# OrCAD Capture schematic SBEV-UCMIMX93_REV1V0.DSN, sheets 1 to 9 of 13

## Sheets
1 01 Index and Block Diagram: title: SBEV-UCMIMX93   01. INDEX AND BLOCK DIAGRAM; rev: 1.0; note: 8000245000
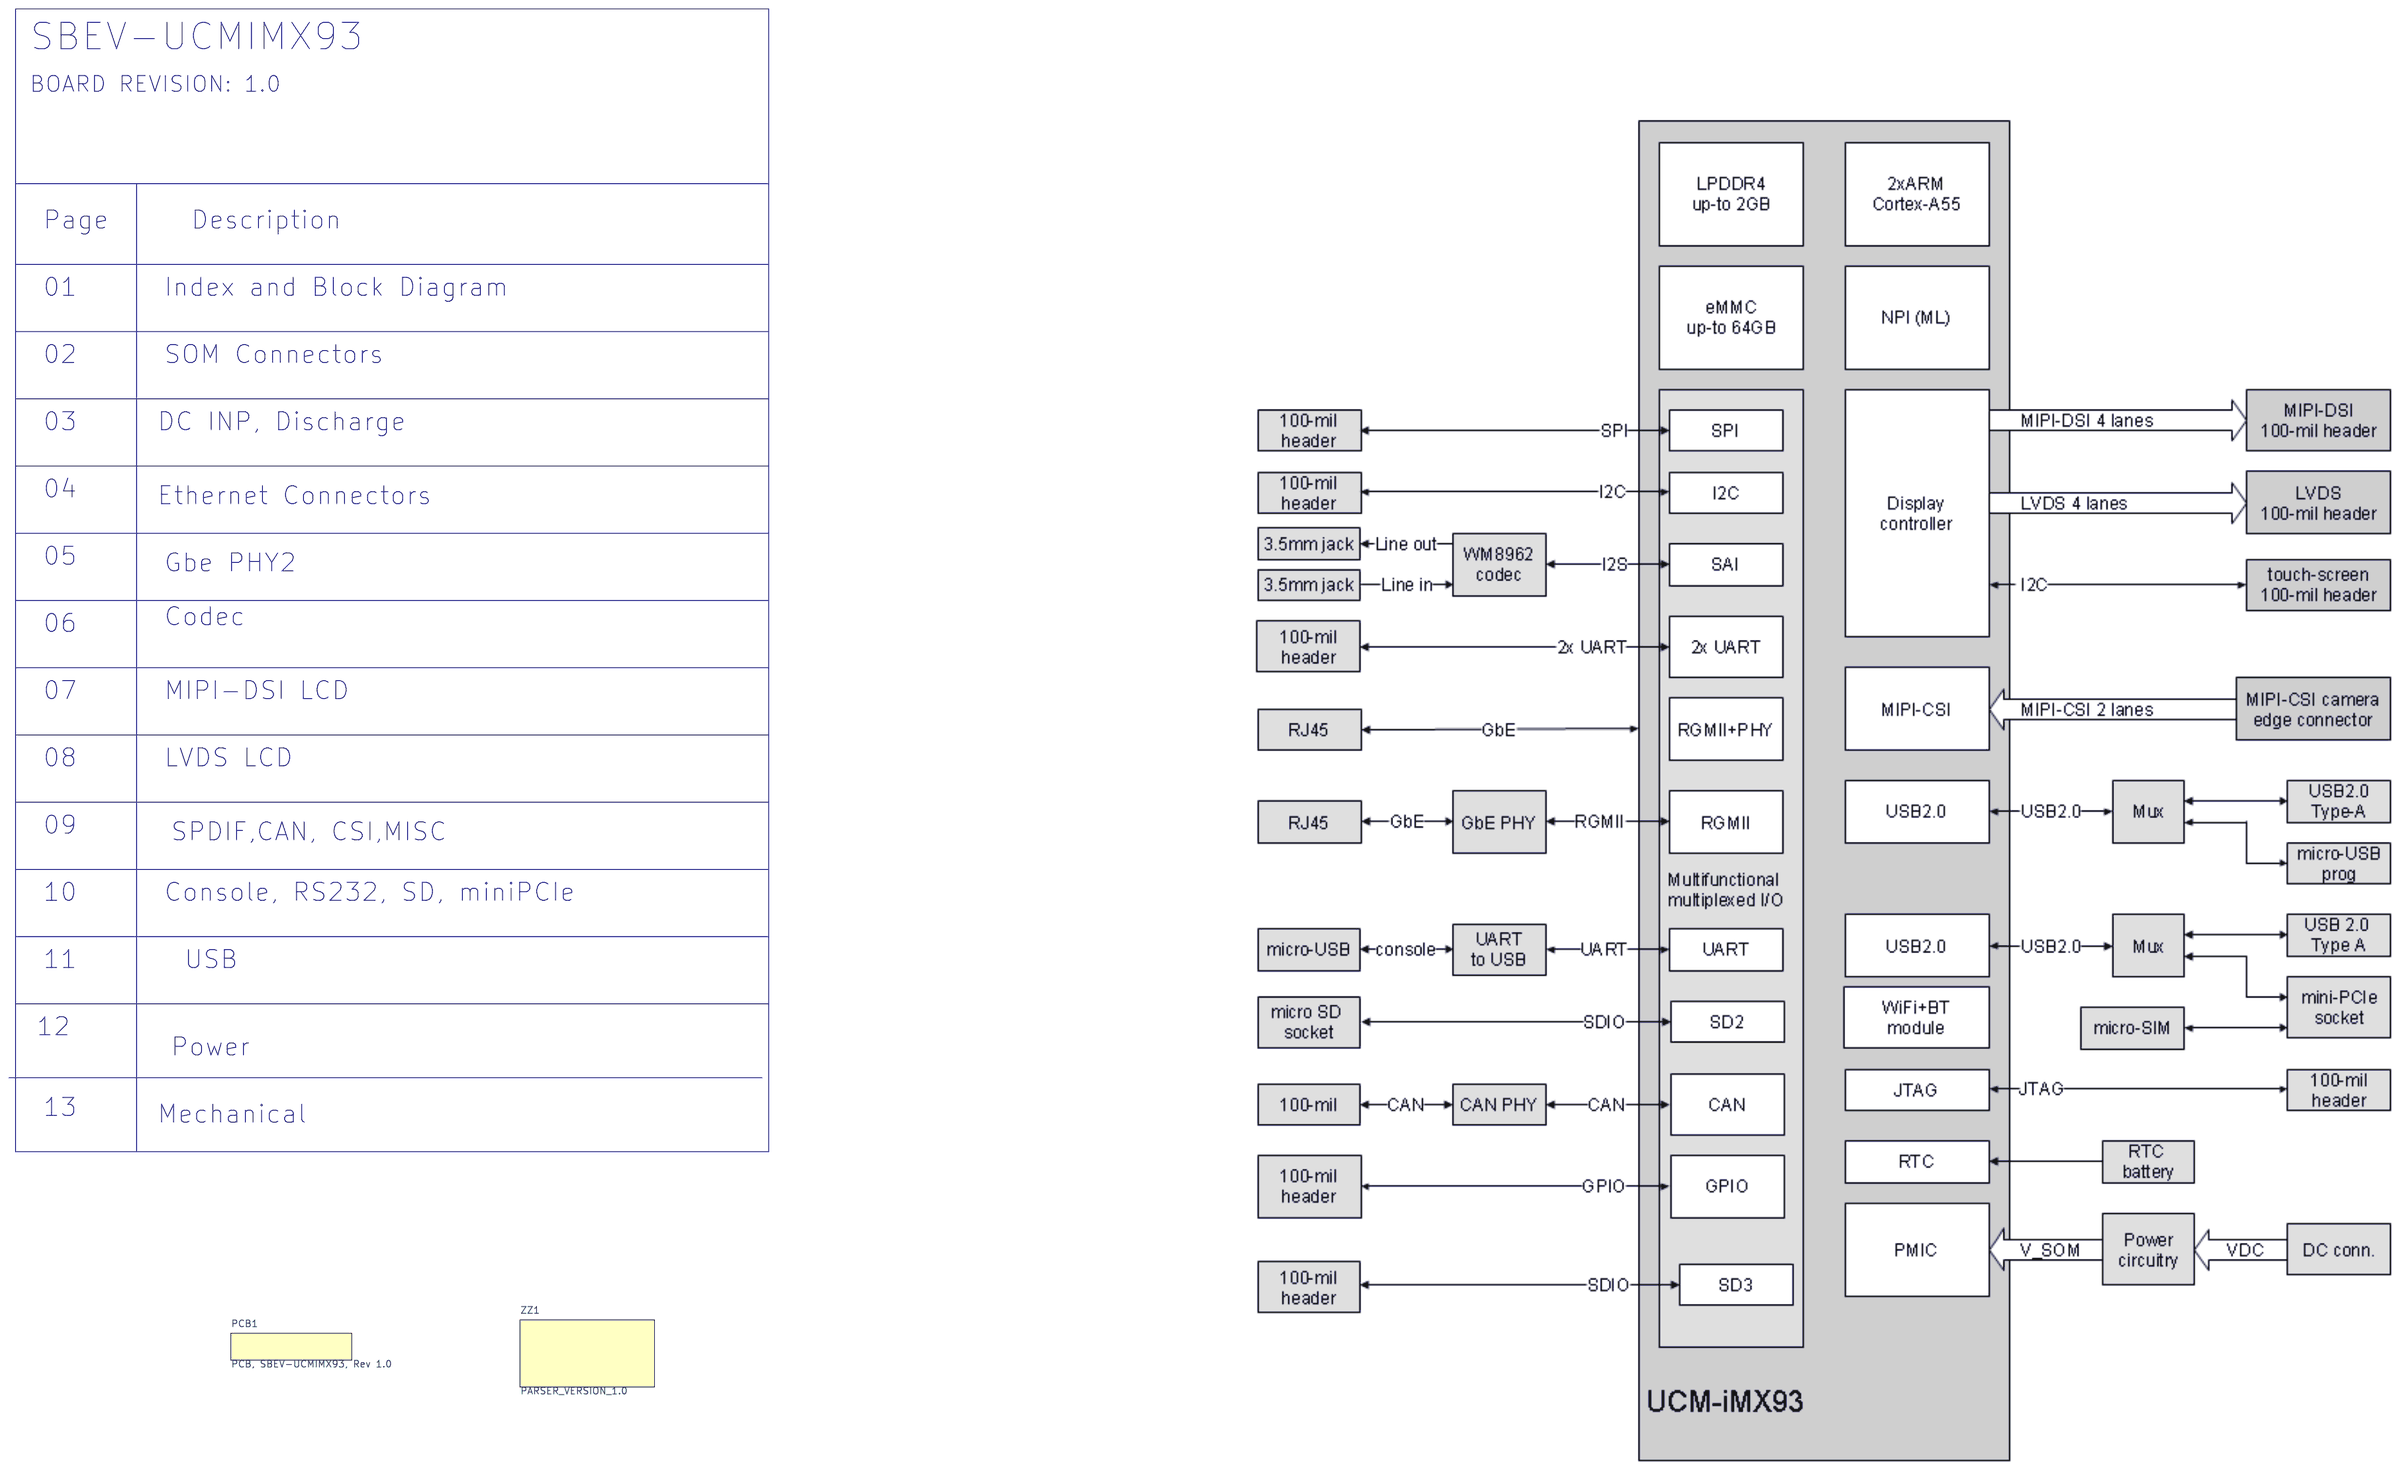
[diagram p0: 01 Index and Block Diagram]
2 02 SOM Connectors: size C; title: SBEV-UCMIMX93   02. SOM CONNECTORS; note: 17 HaYetsira Street; note: Yokneam Illit, Israel 2069208
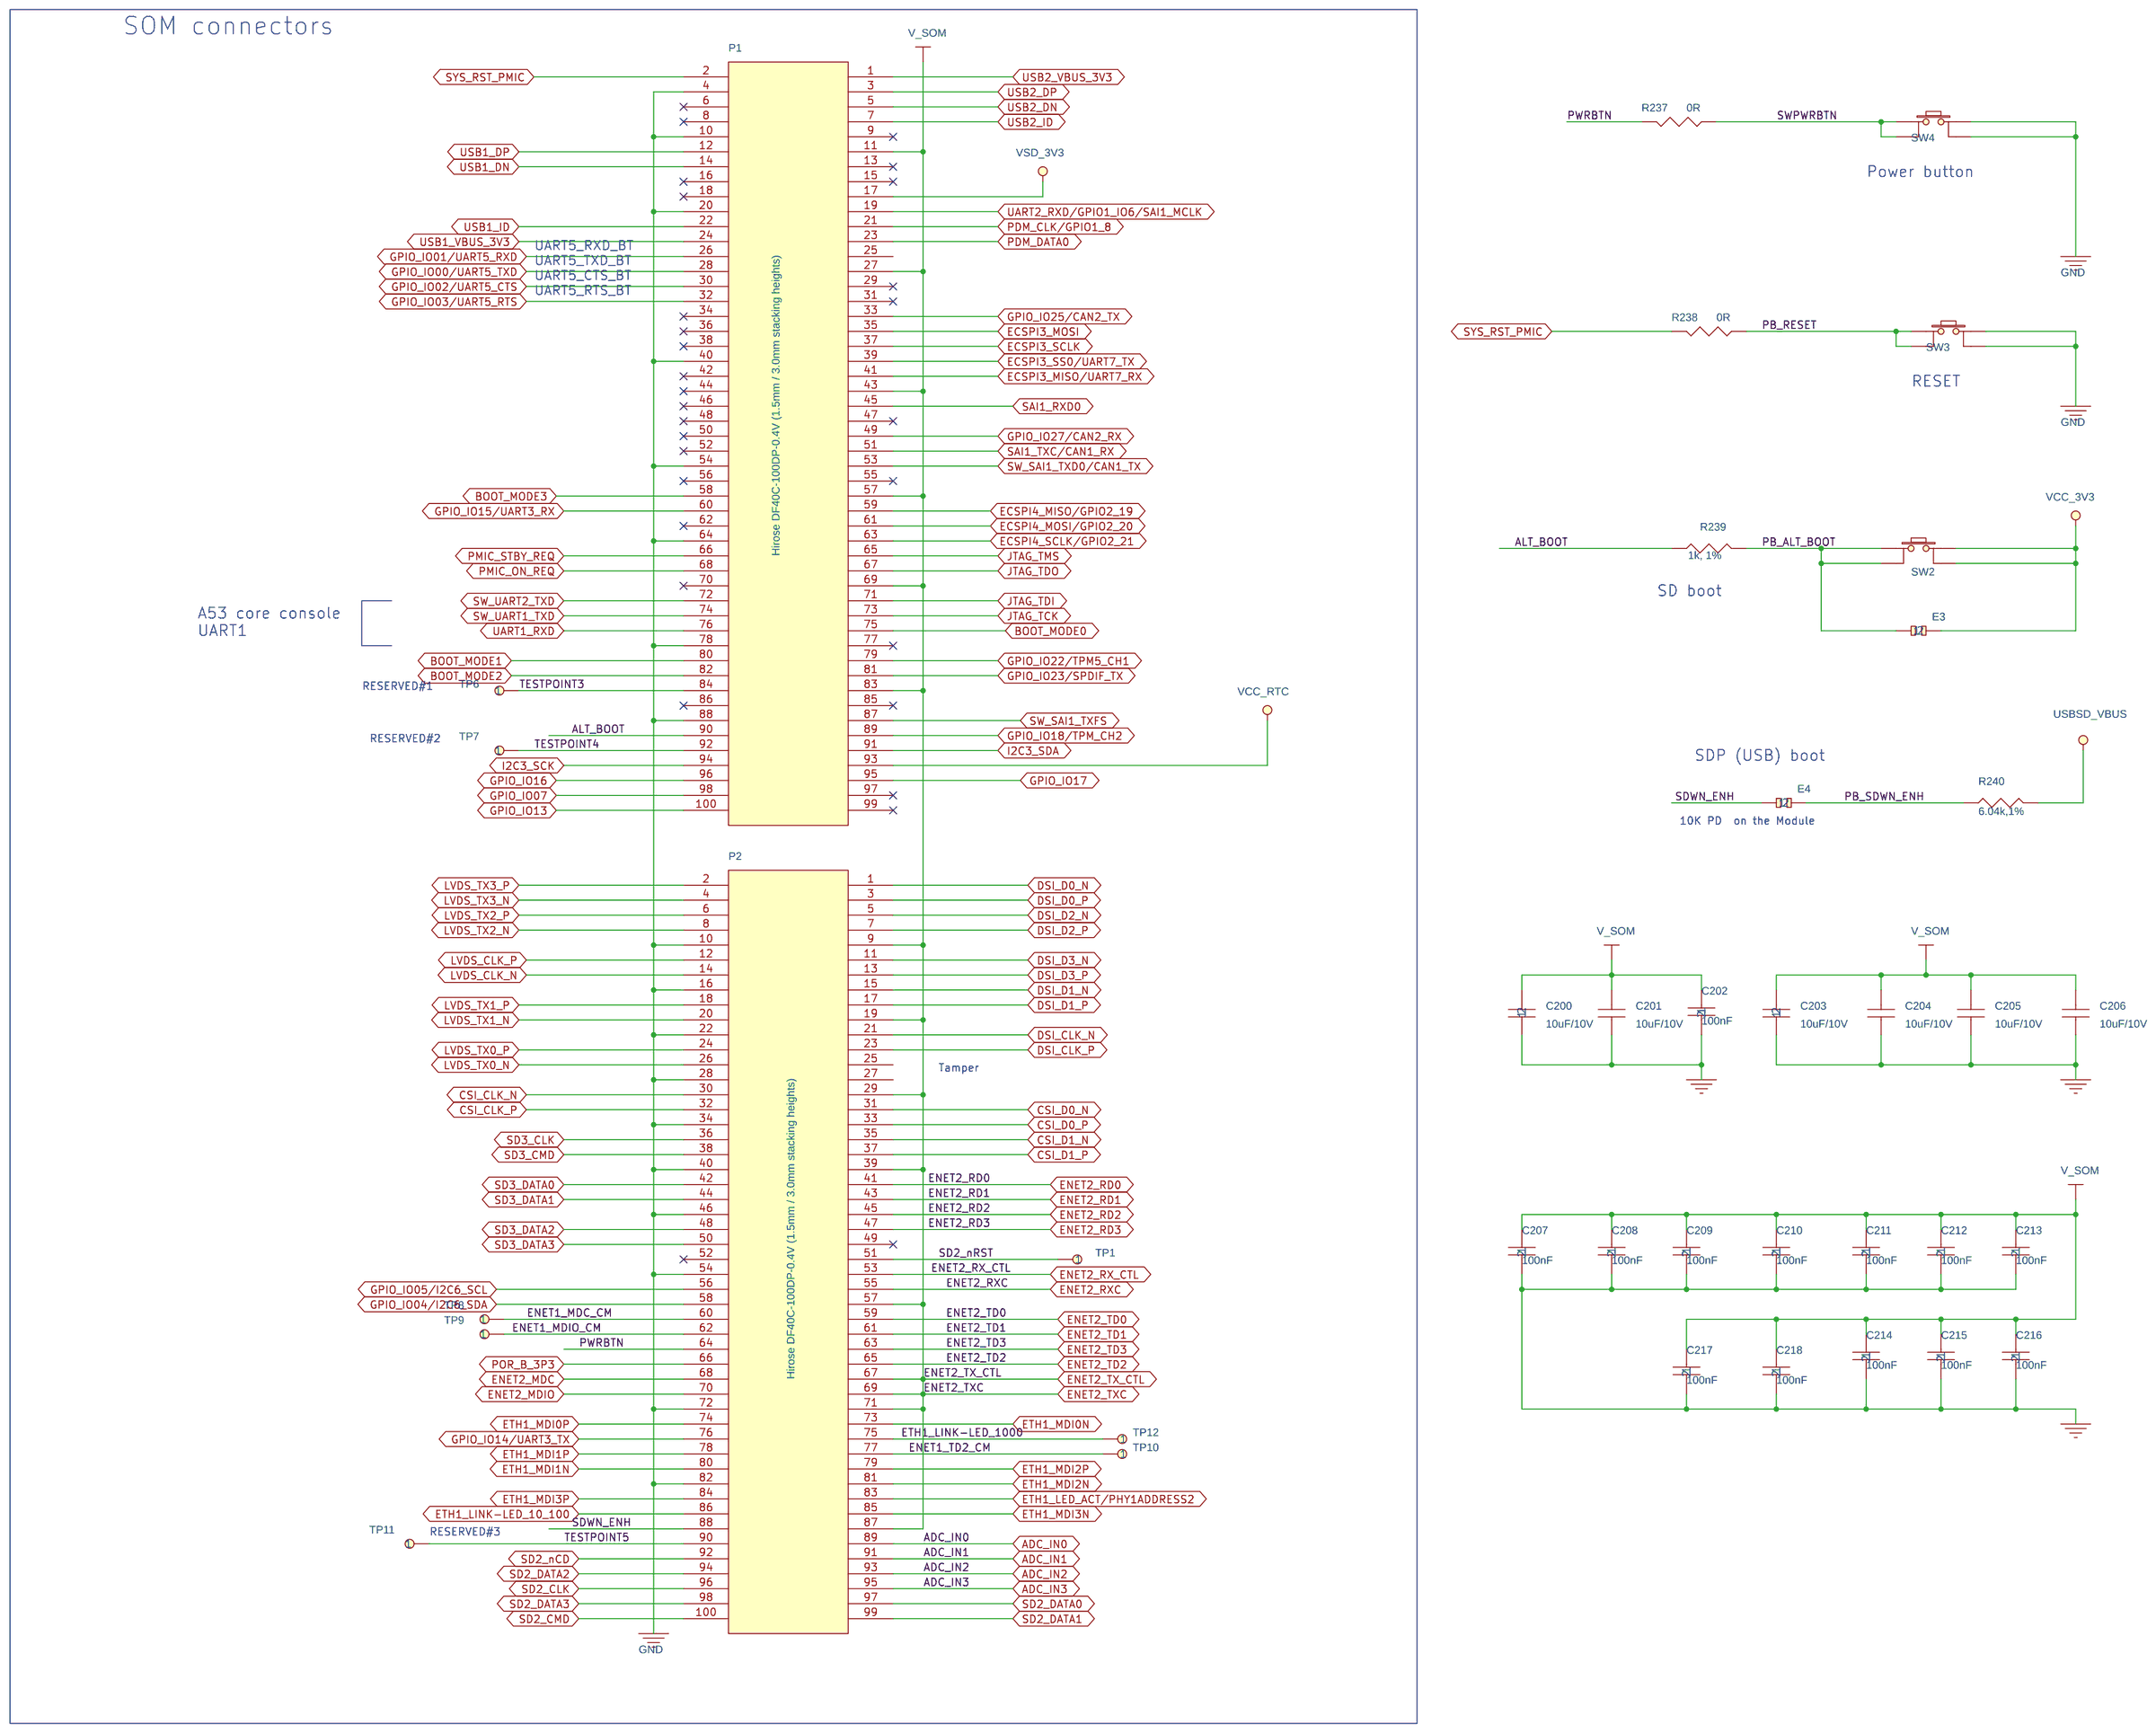
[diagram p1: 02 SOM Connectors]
3 03 DC INP, Discharge: size B; title: SBEV-UCMIMX93   03. DC INP, Discharge; company: CompuLab Ltd.  (972) 4 8238567; note: 17 HaYetsira Street; note: Yokneam Illit, Israel 2069208
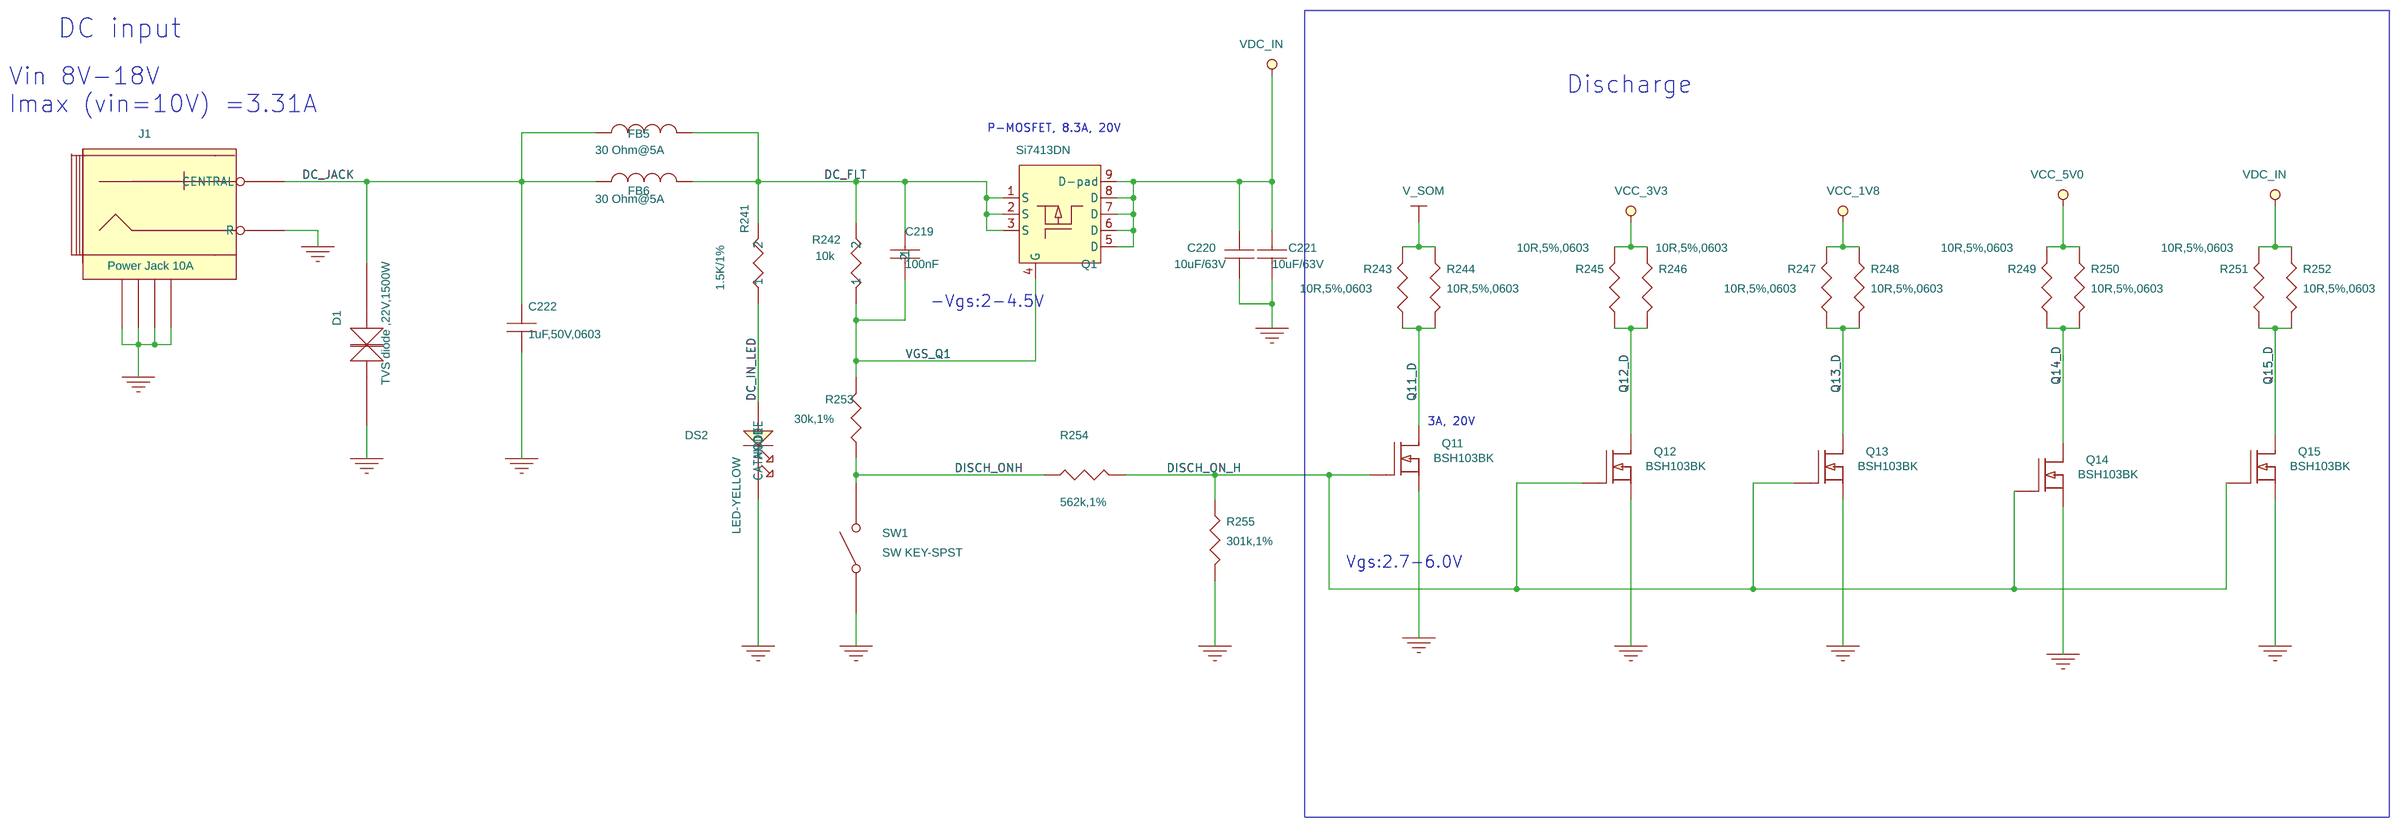
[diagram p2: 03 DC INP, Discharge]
4 04 Ethernet  connectors: size B; title: SBEV-UCMIMX93      04. Ethernet connectors
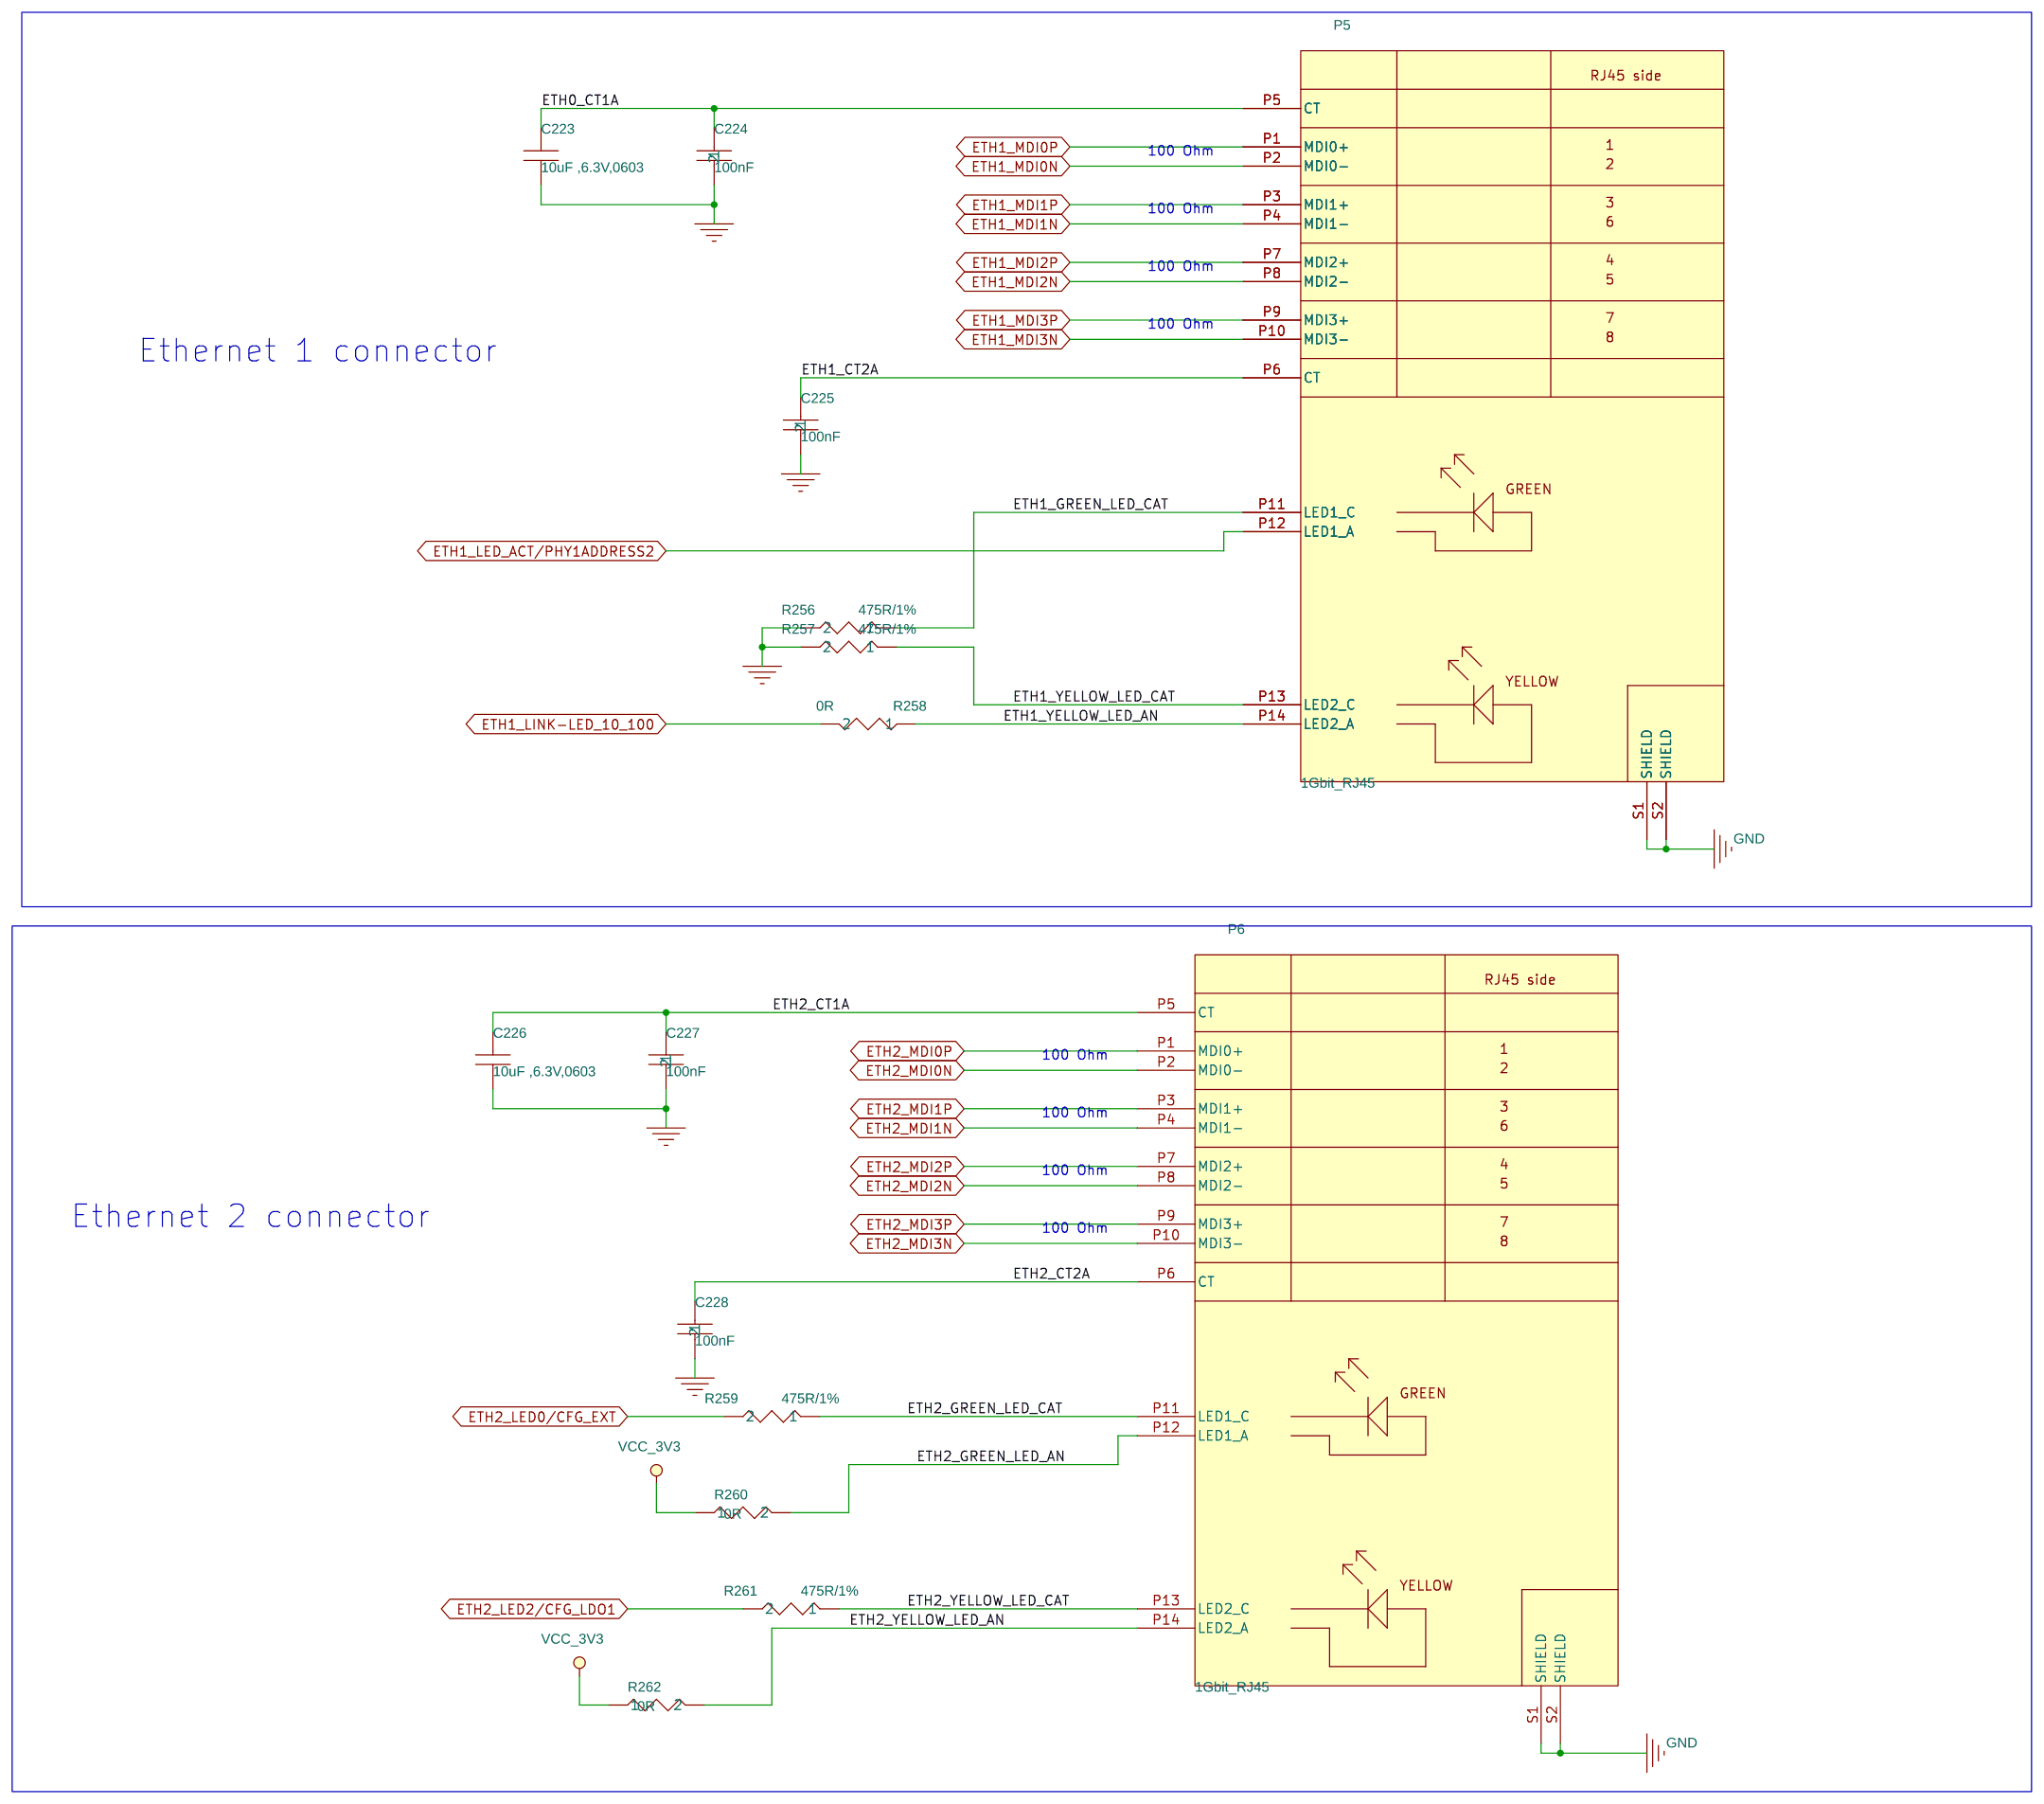
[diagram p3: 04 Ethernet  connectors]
5 11 USB: size C; title: SBEV-UCMIMX93   11. USB
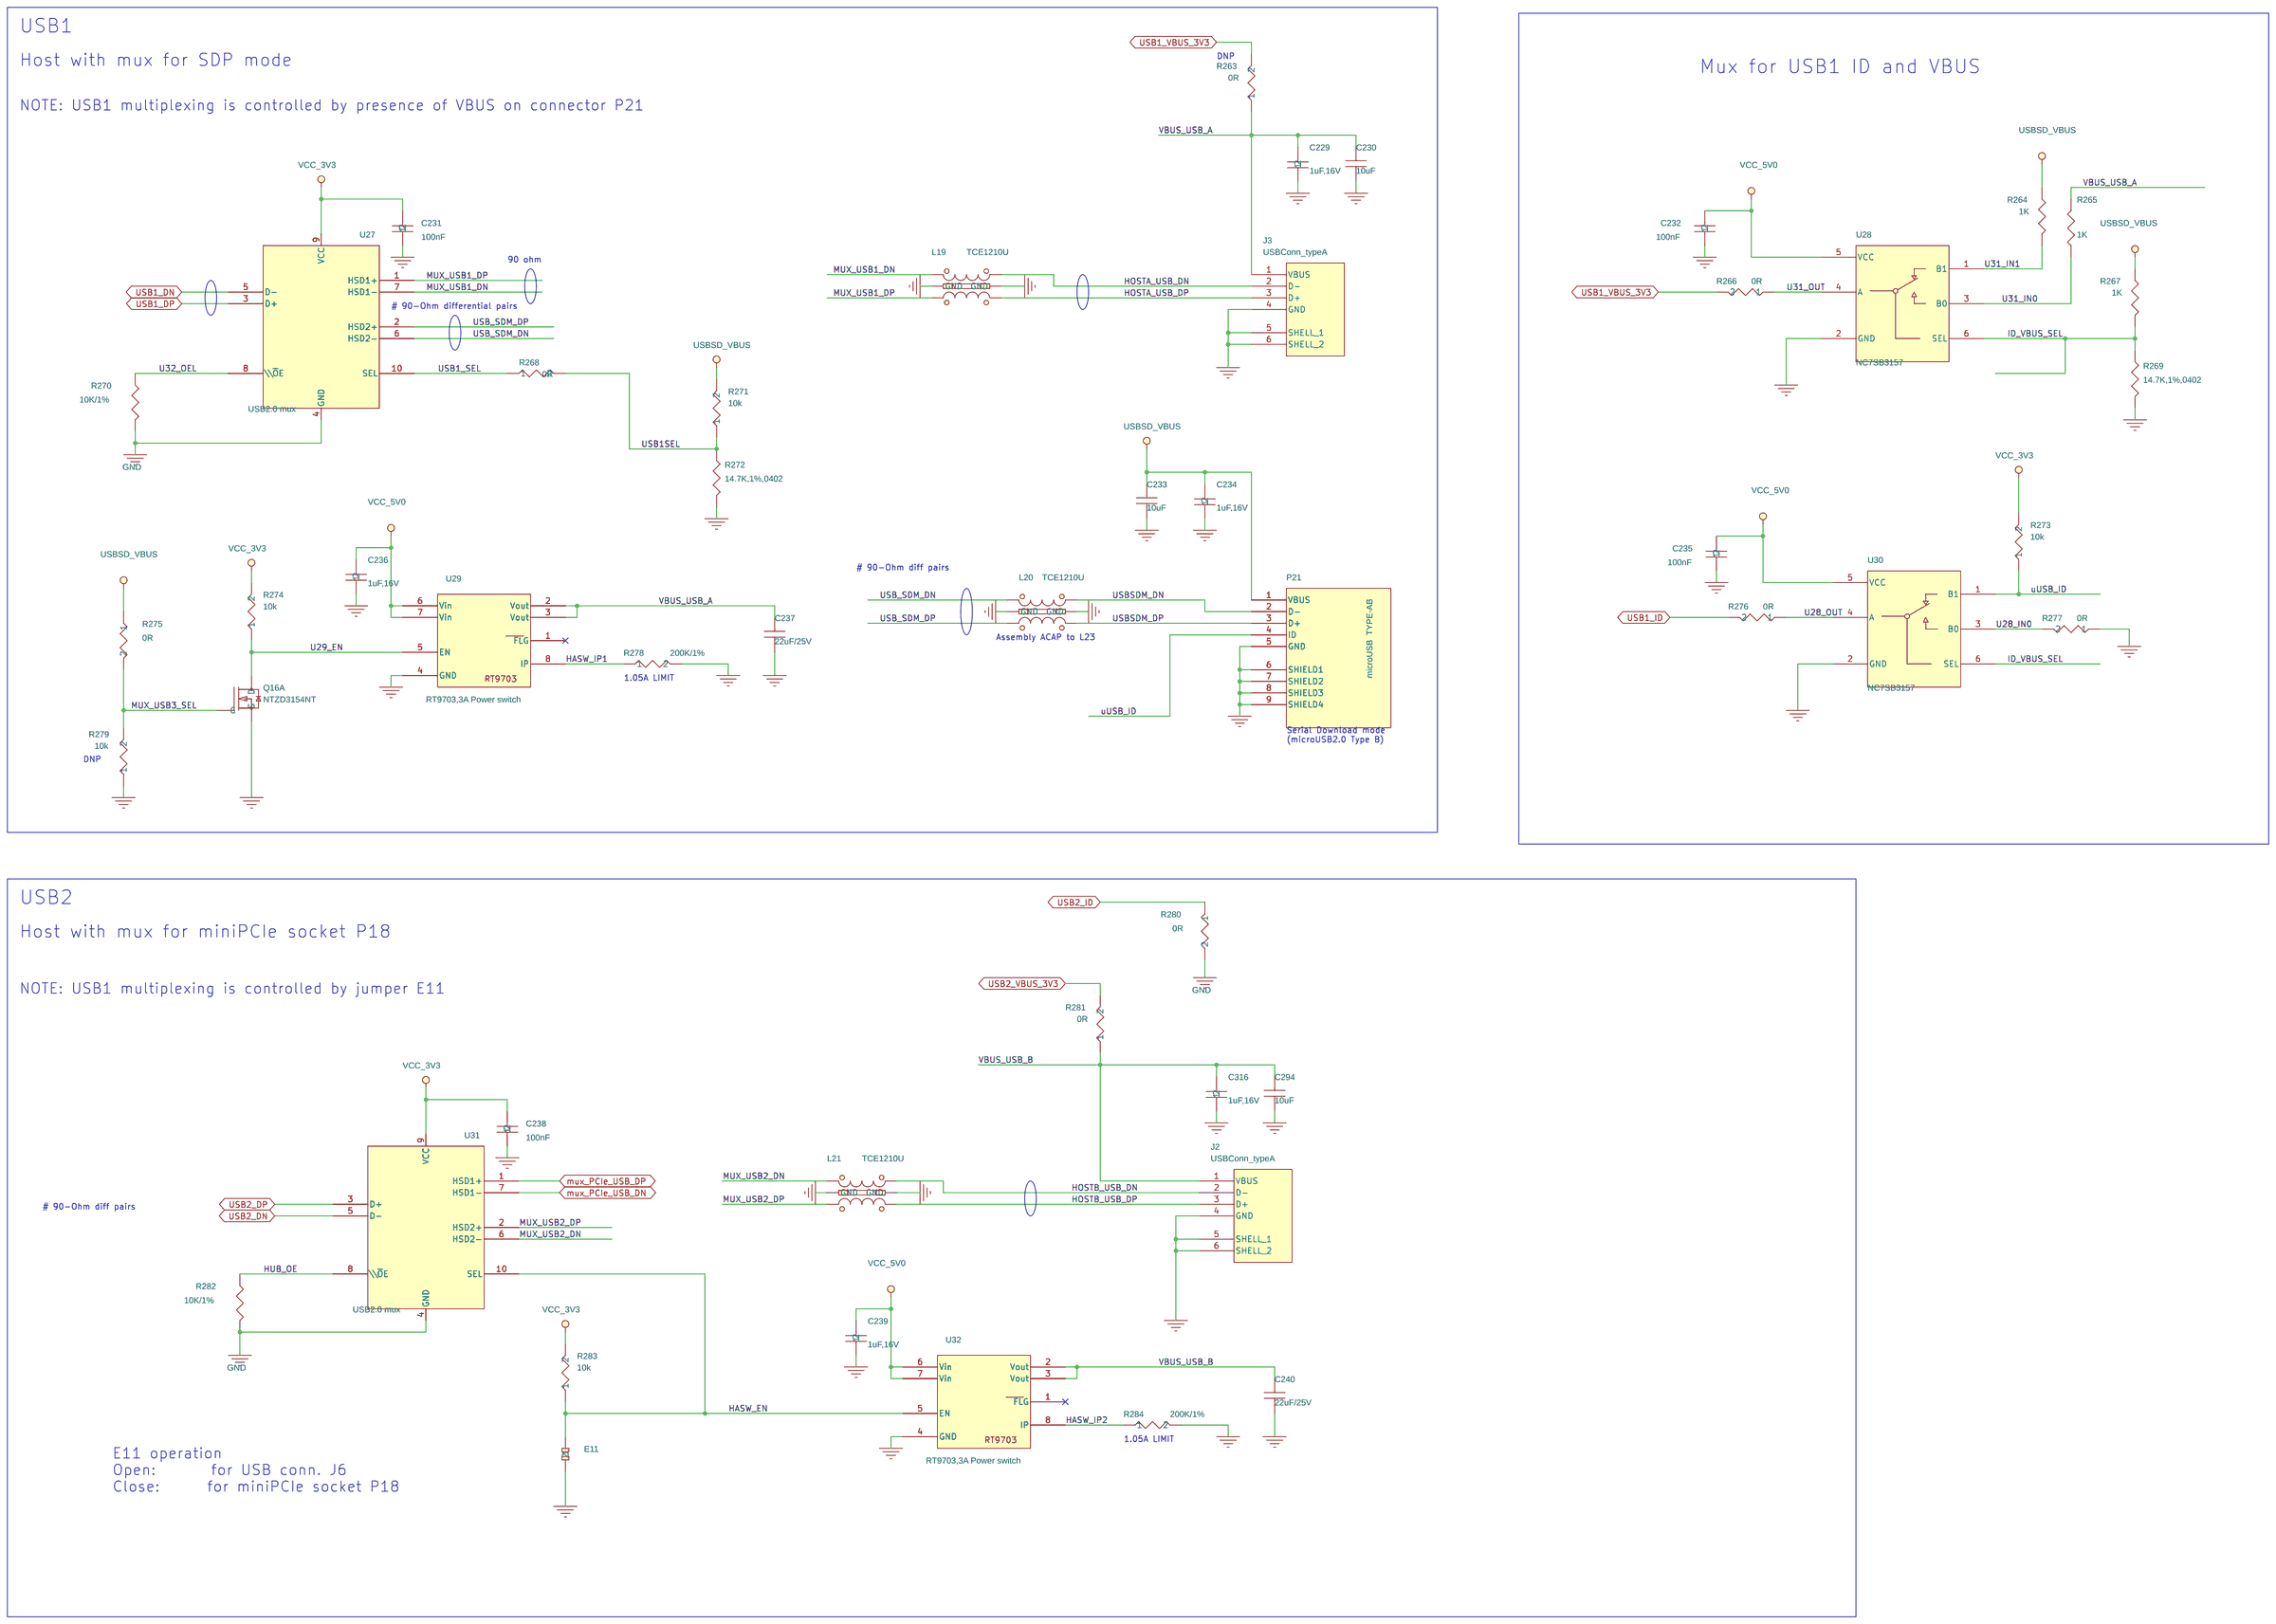
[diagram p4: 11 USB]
6 09  SPDIF,CAN, CSI,MISC: size C; title: SBEV-UCMIMX93      9. SPDIF,CAN, CSI,MISC
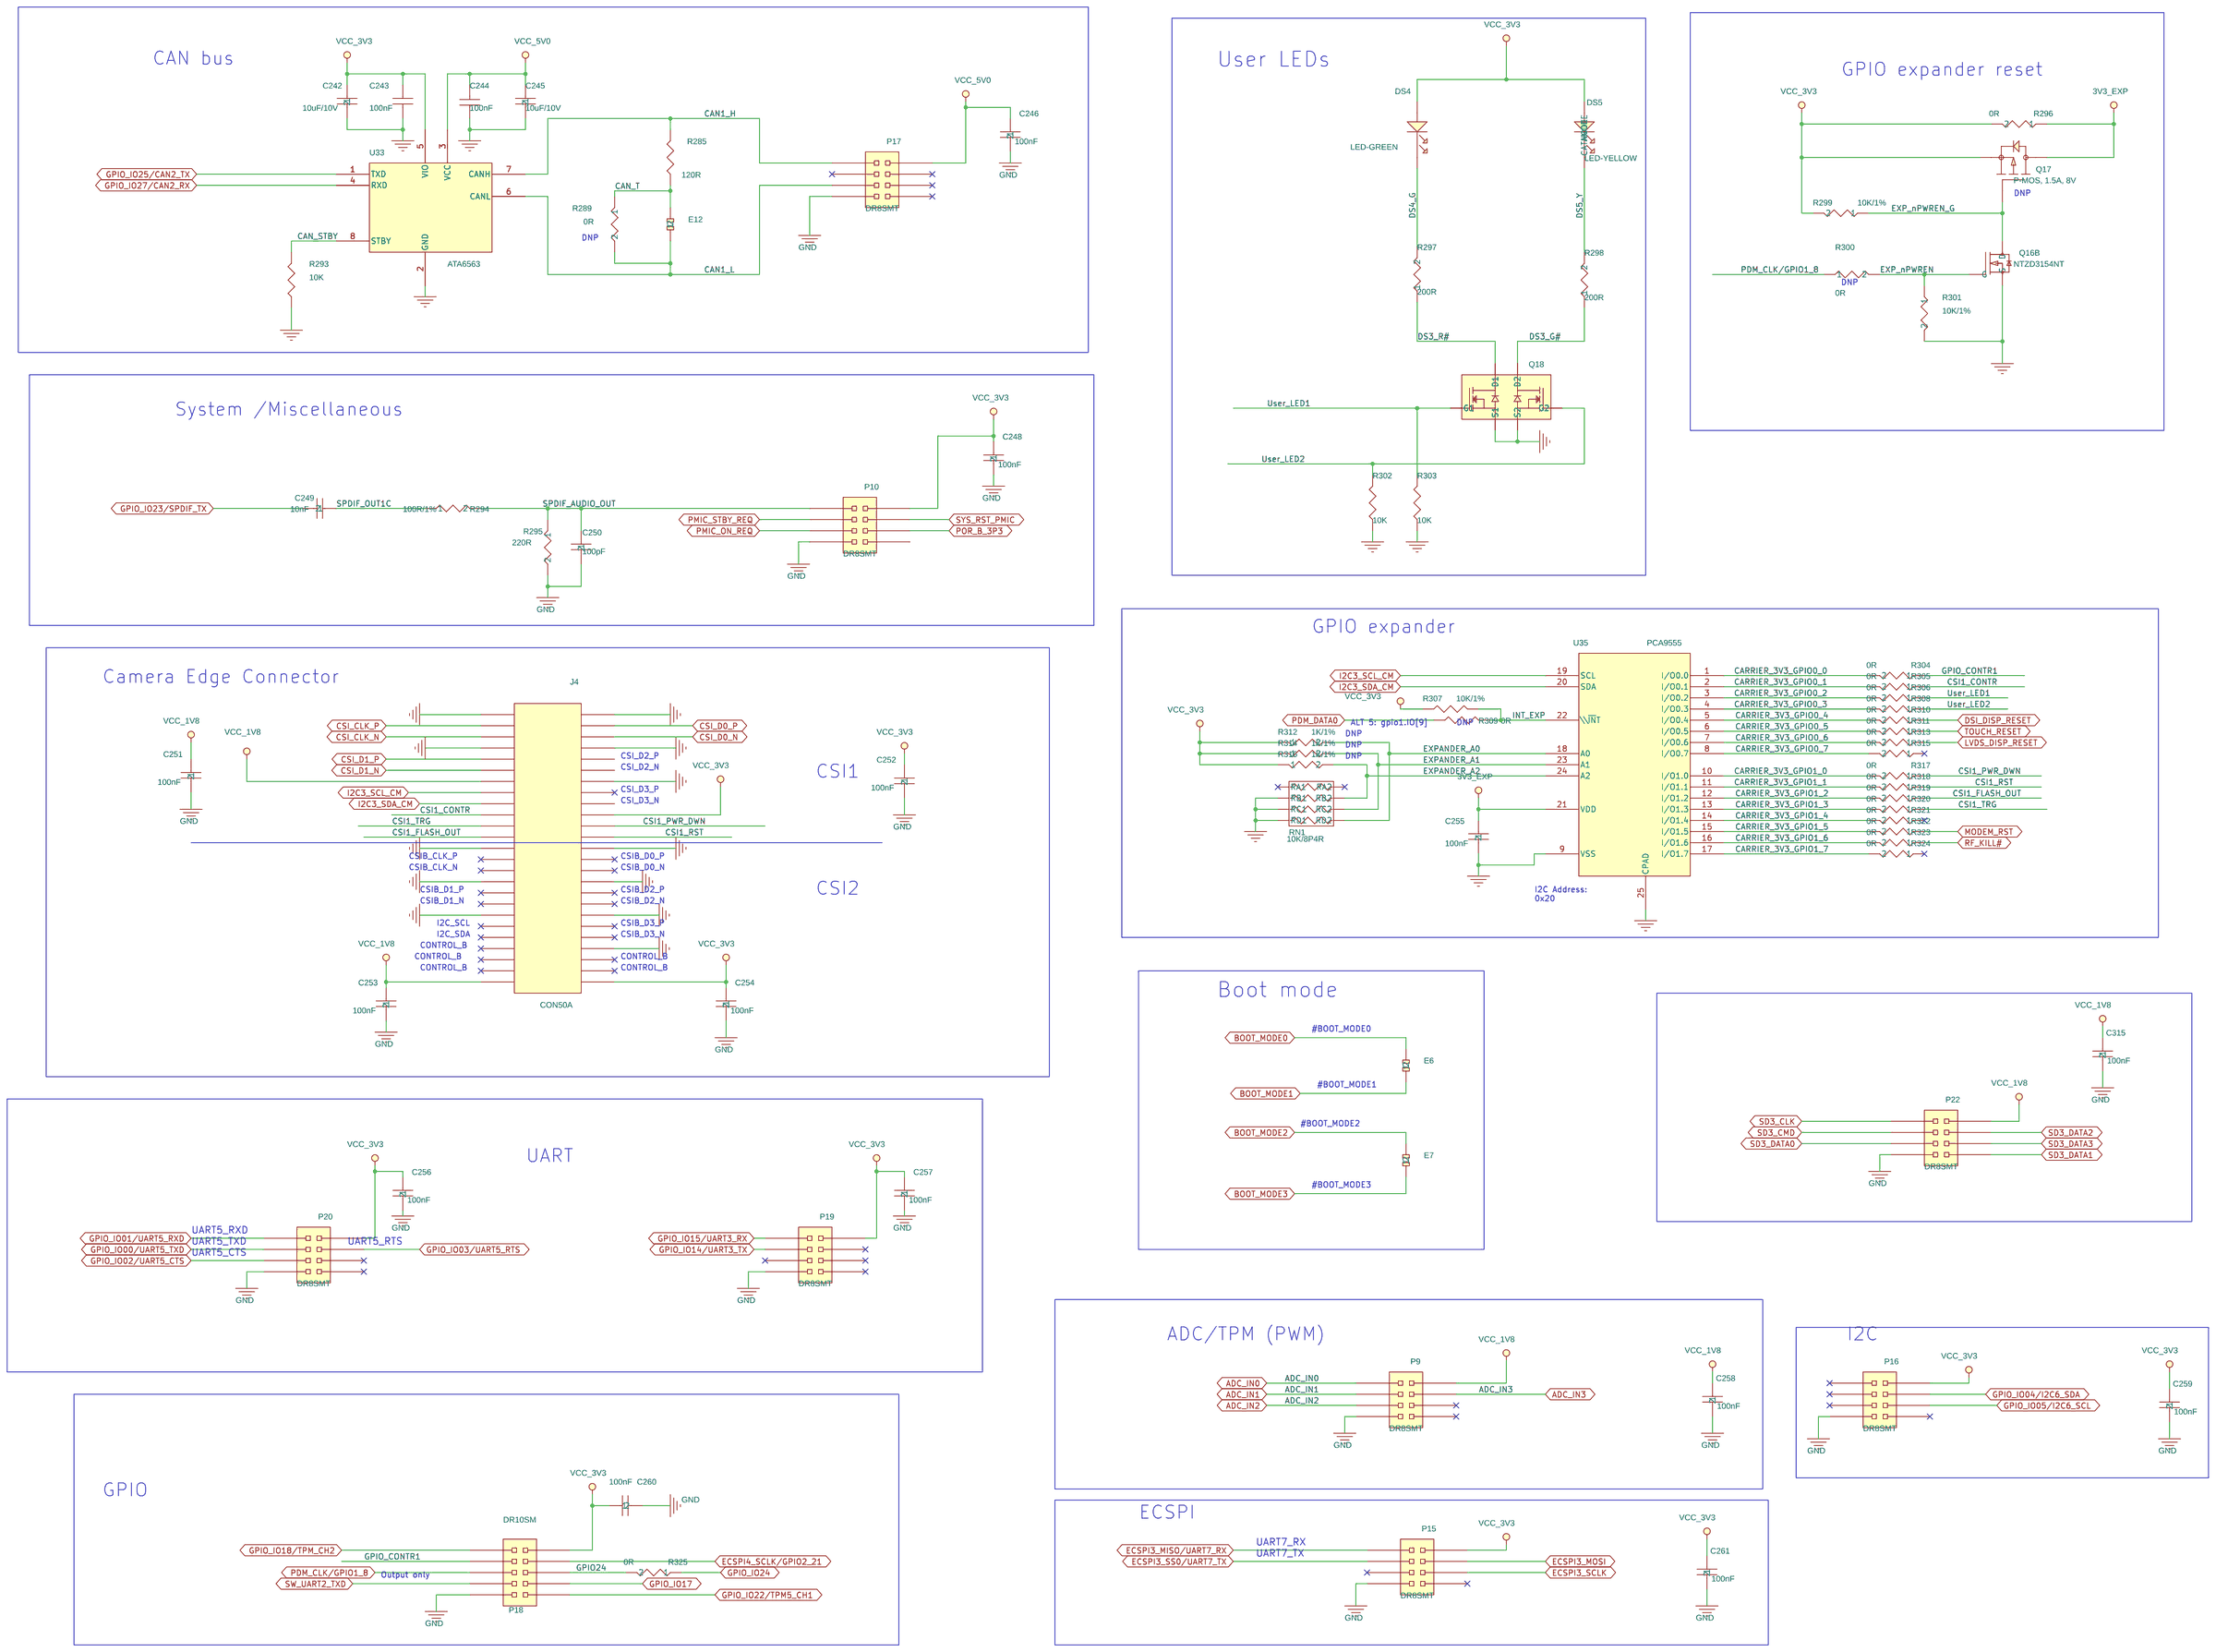
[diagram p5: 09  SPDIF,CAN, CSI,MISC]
7 06 Codec: size C; title: SBEV-UCMIMX93  06. Codec
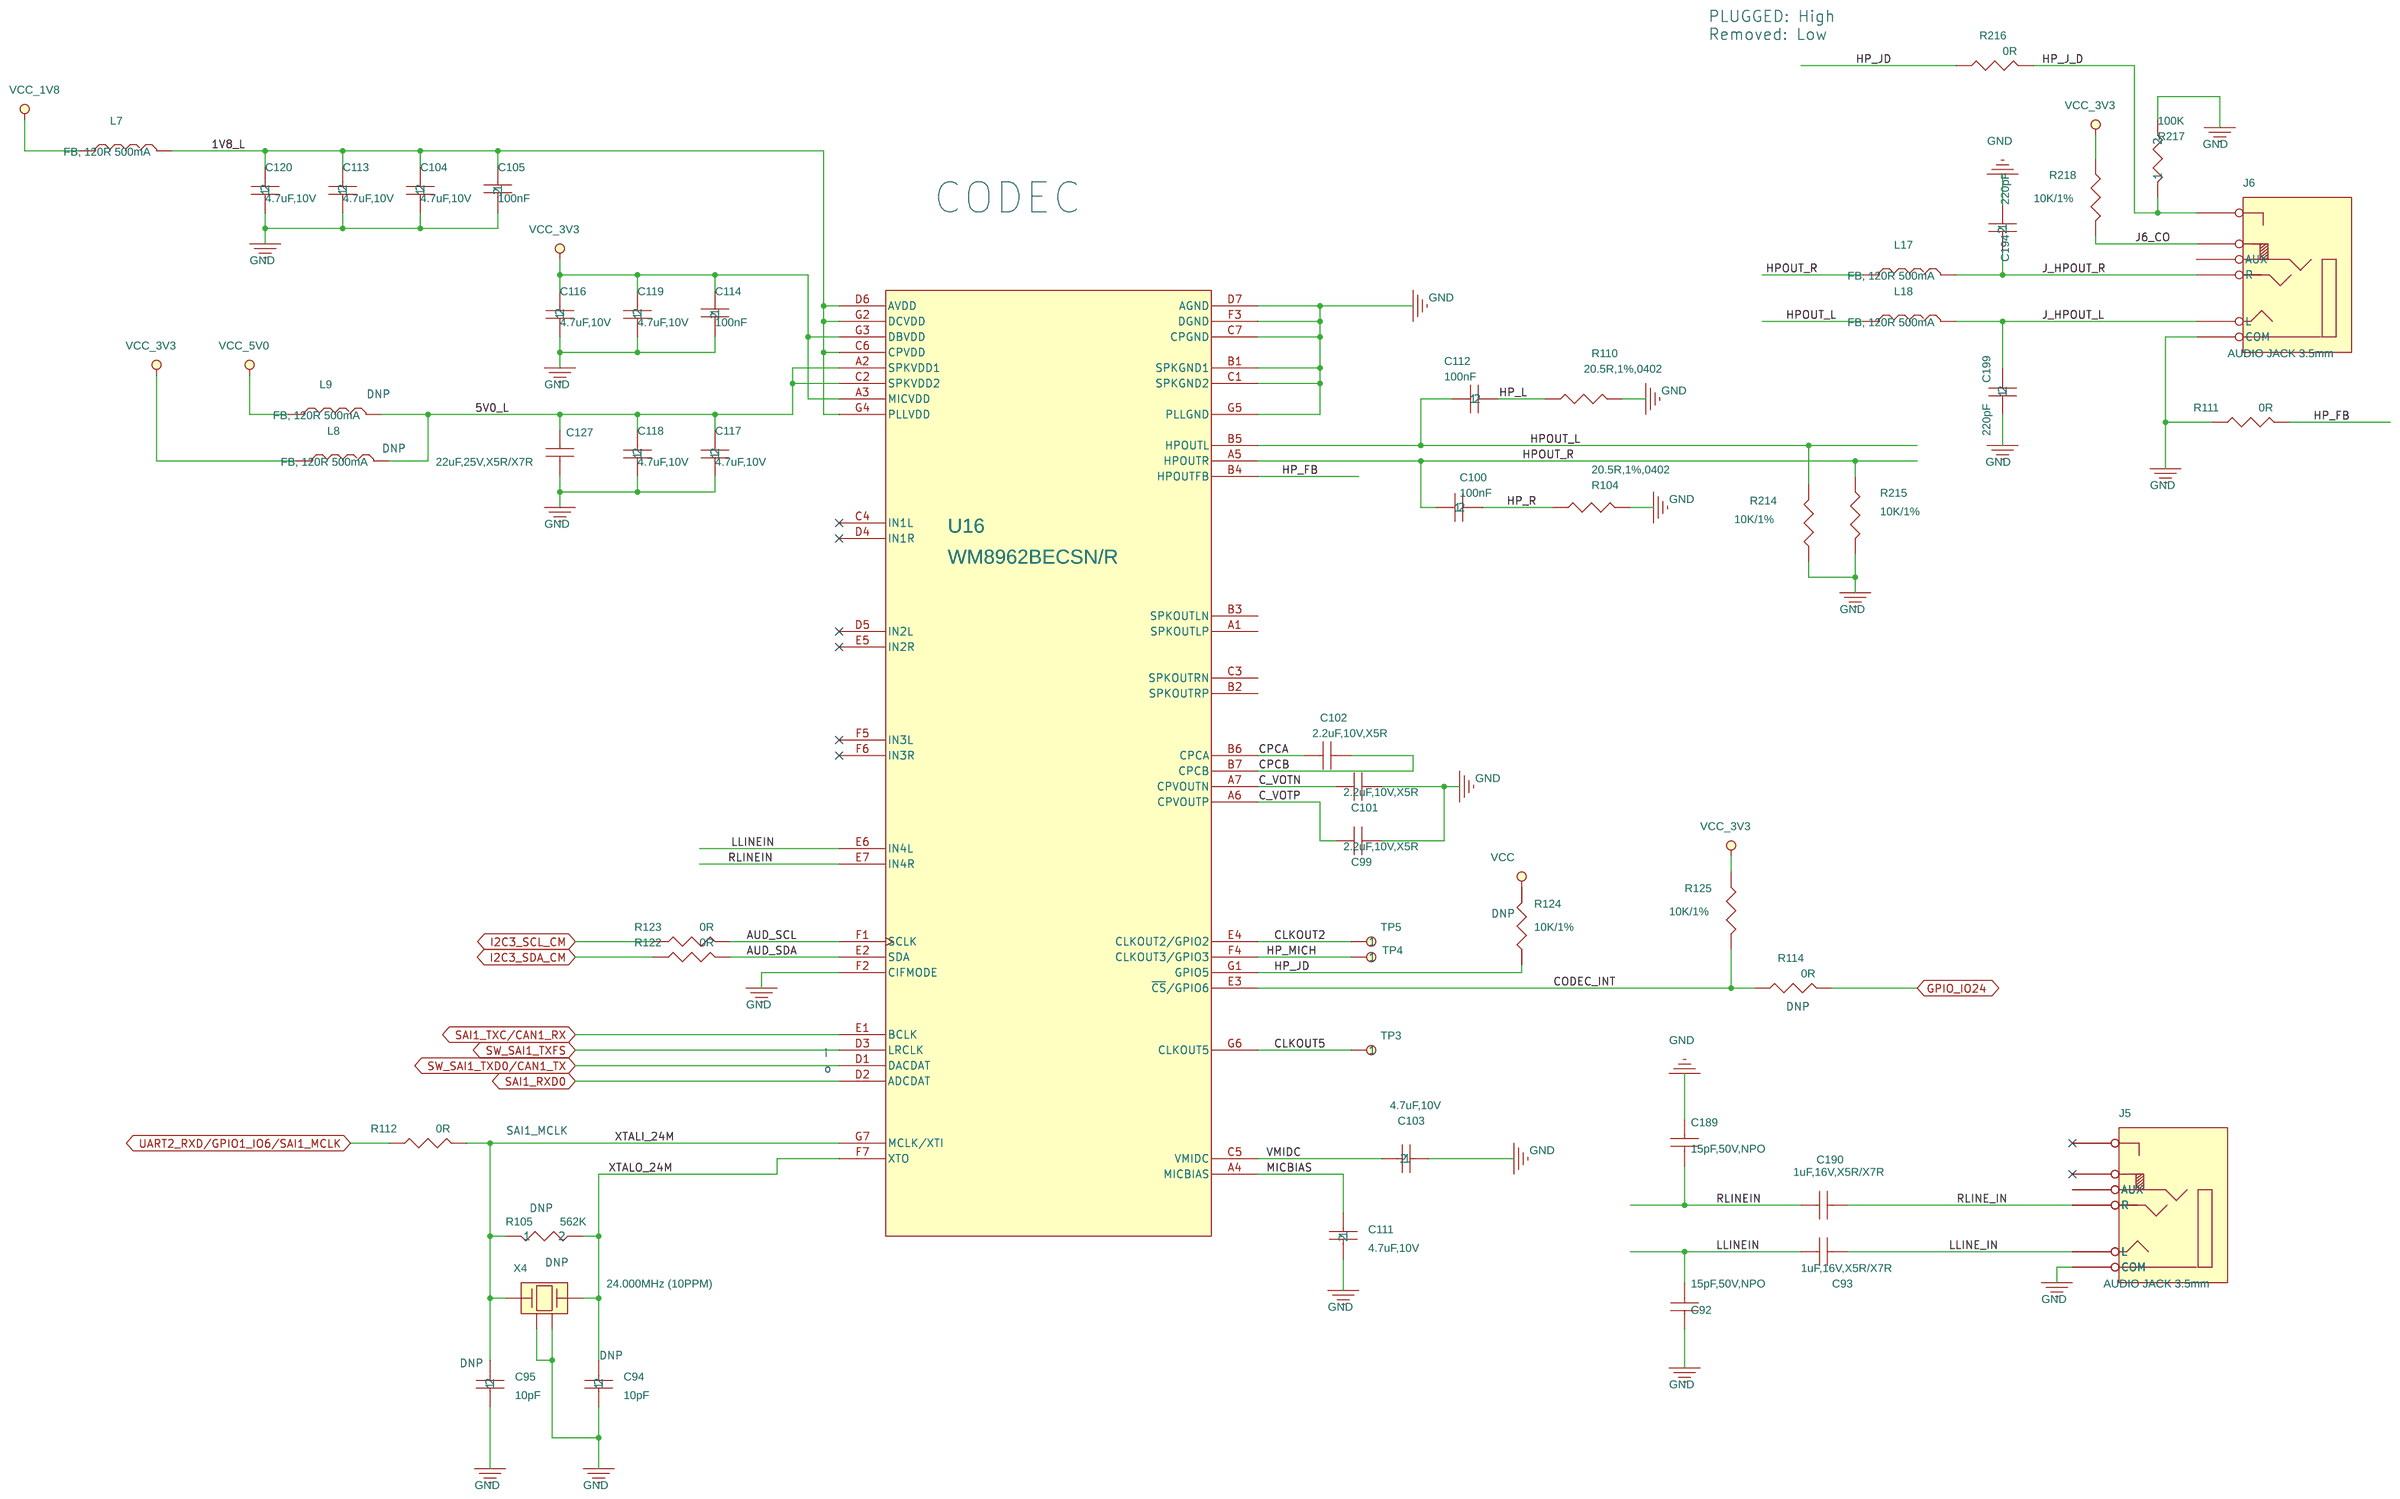
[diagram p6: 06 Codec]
8 07 MIPI-DSI LCD: size B; title: SBEV-UCMIMX93   07. MIPI-DSI LCD
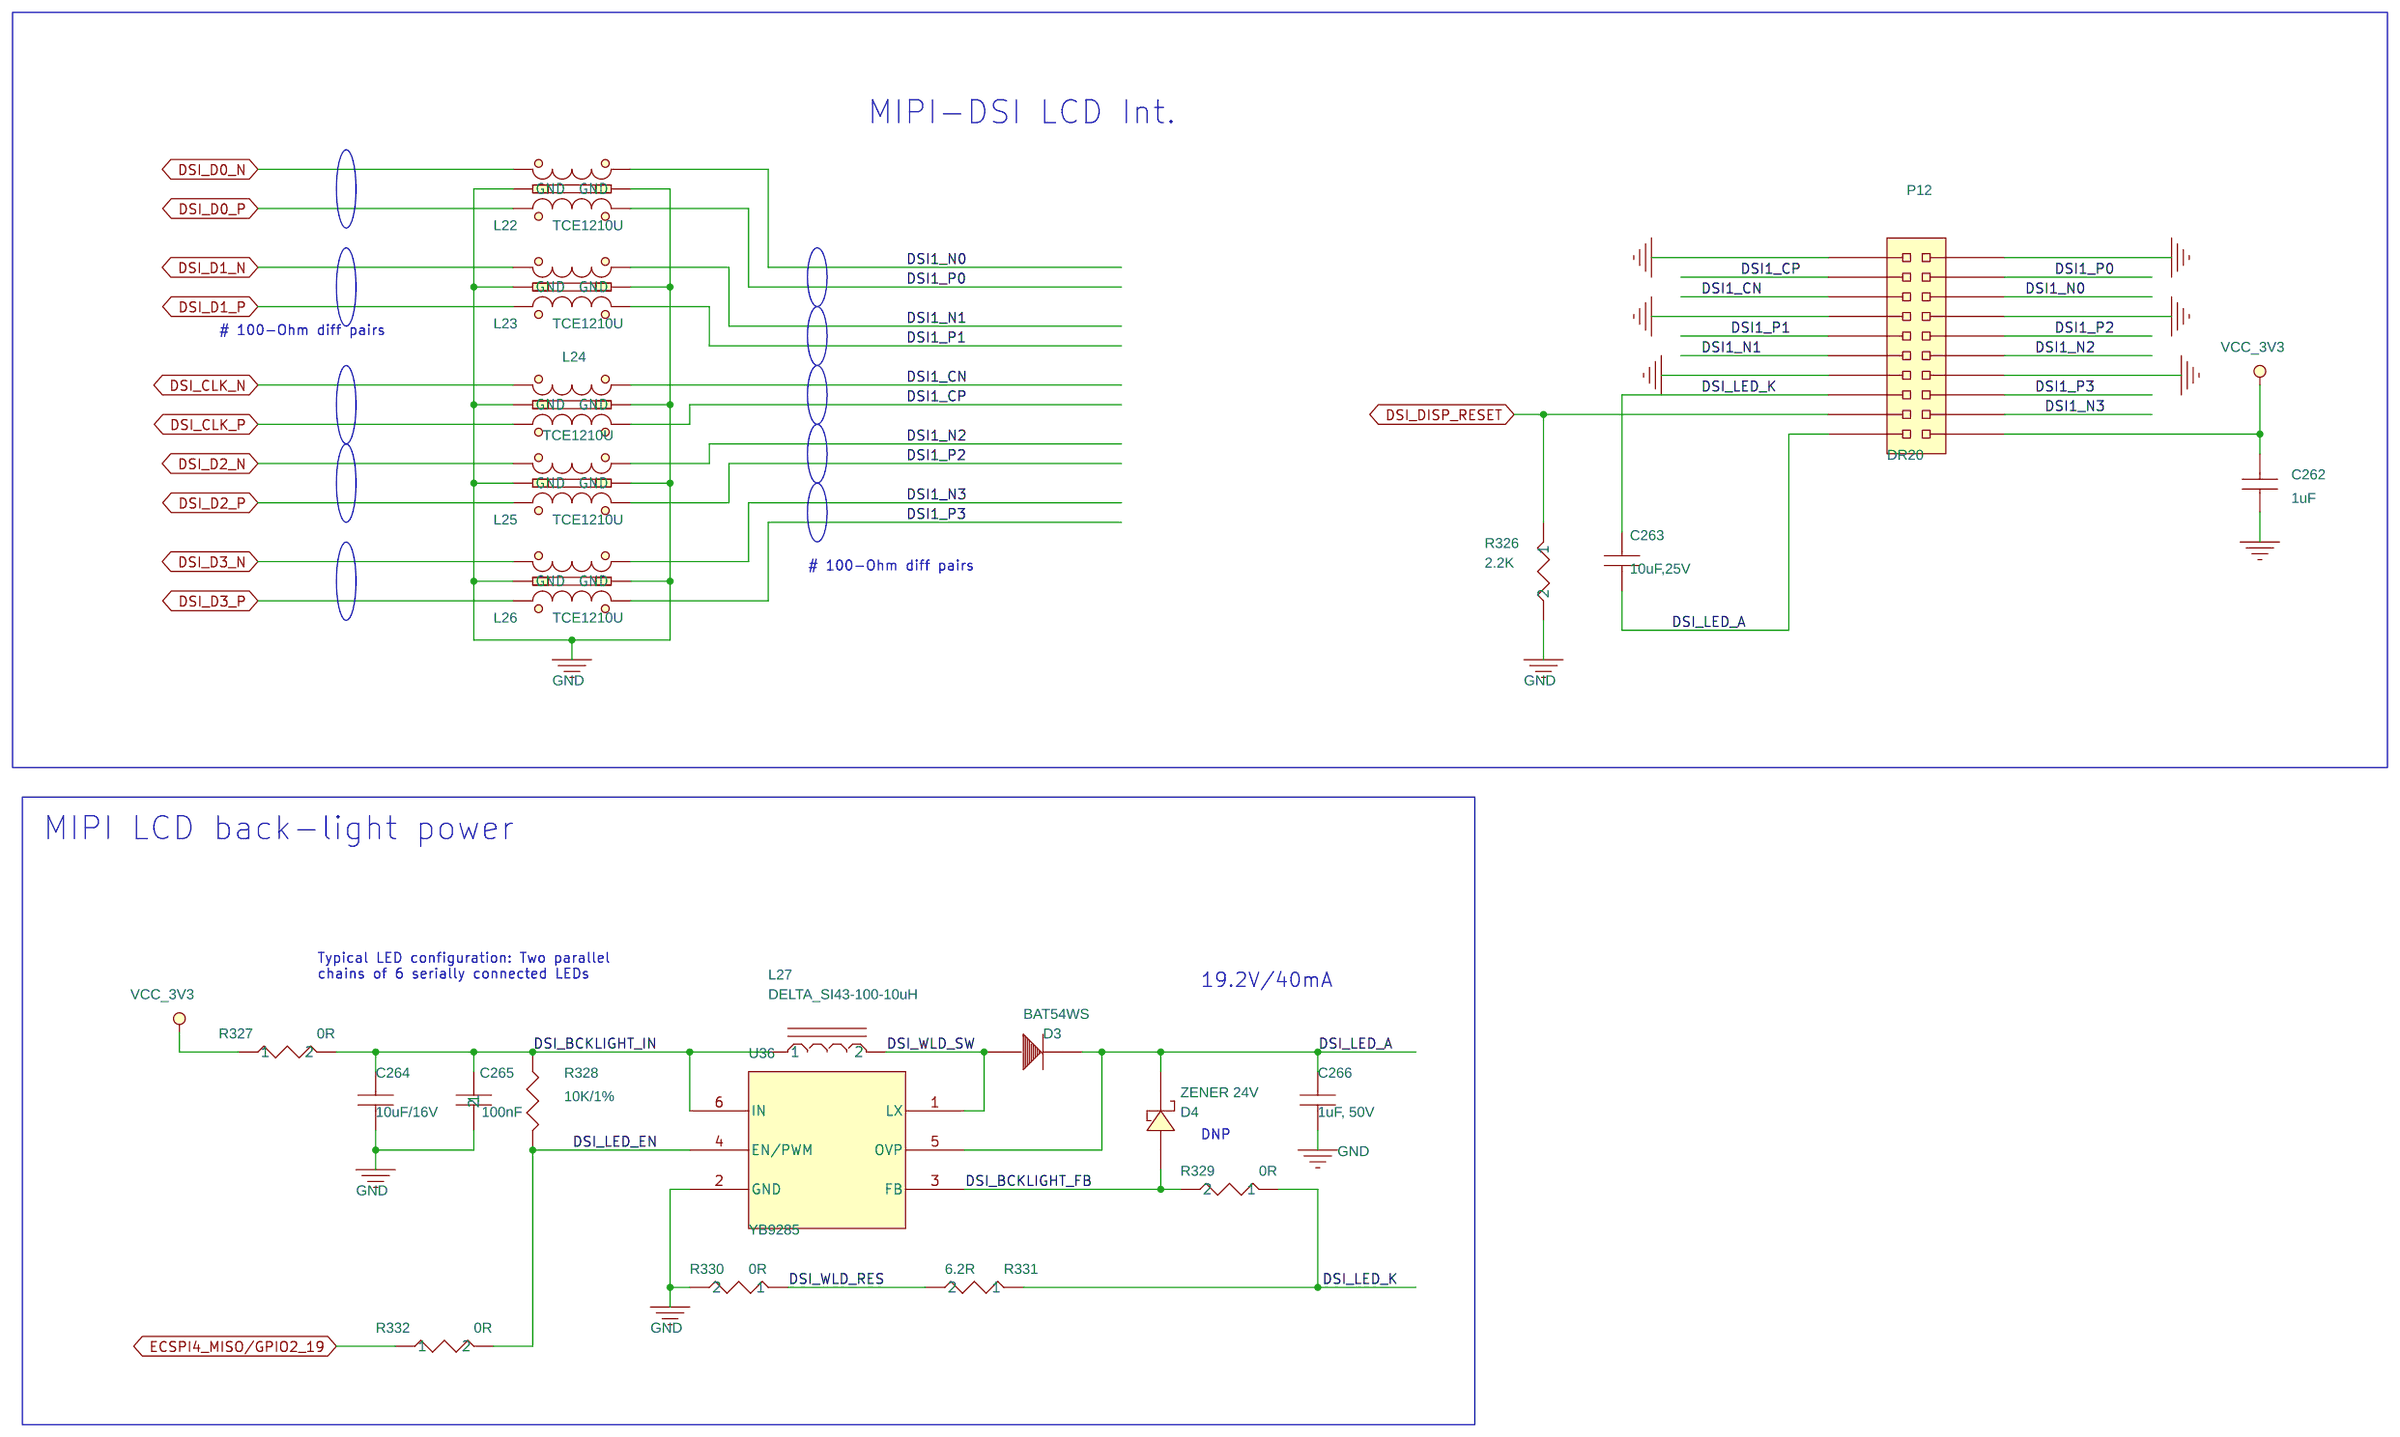
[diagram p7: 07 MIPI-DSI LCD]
9 08 LVDS LCD: size B; title: SBEV-UCMIMX93   08. LVDS LCD
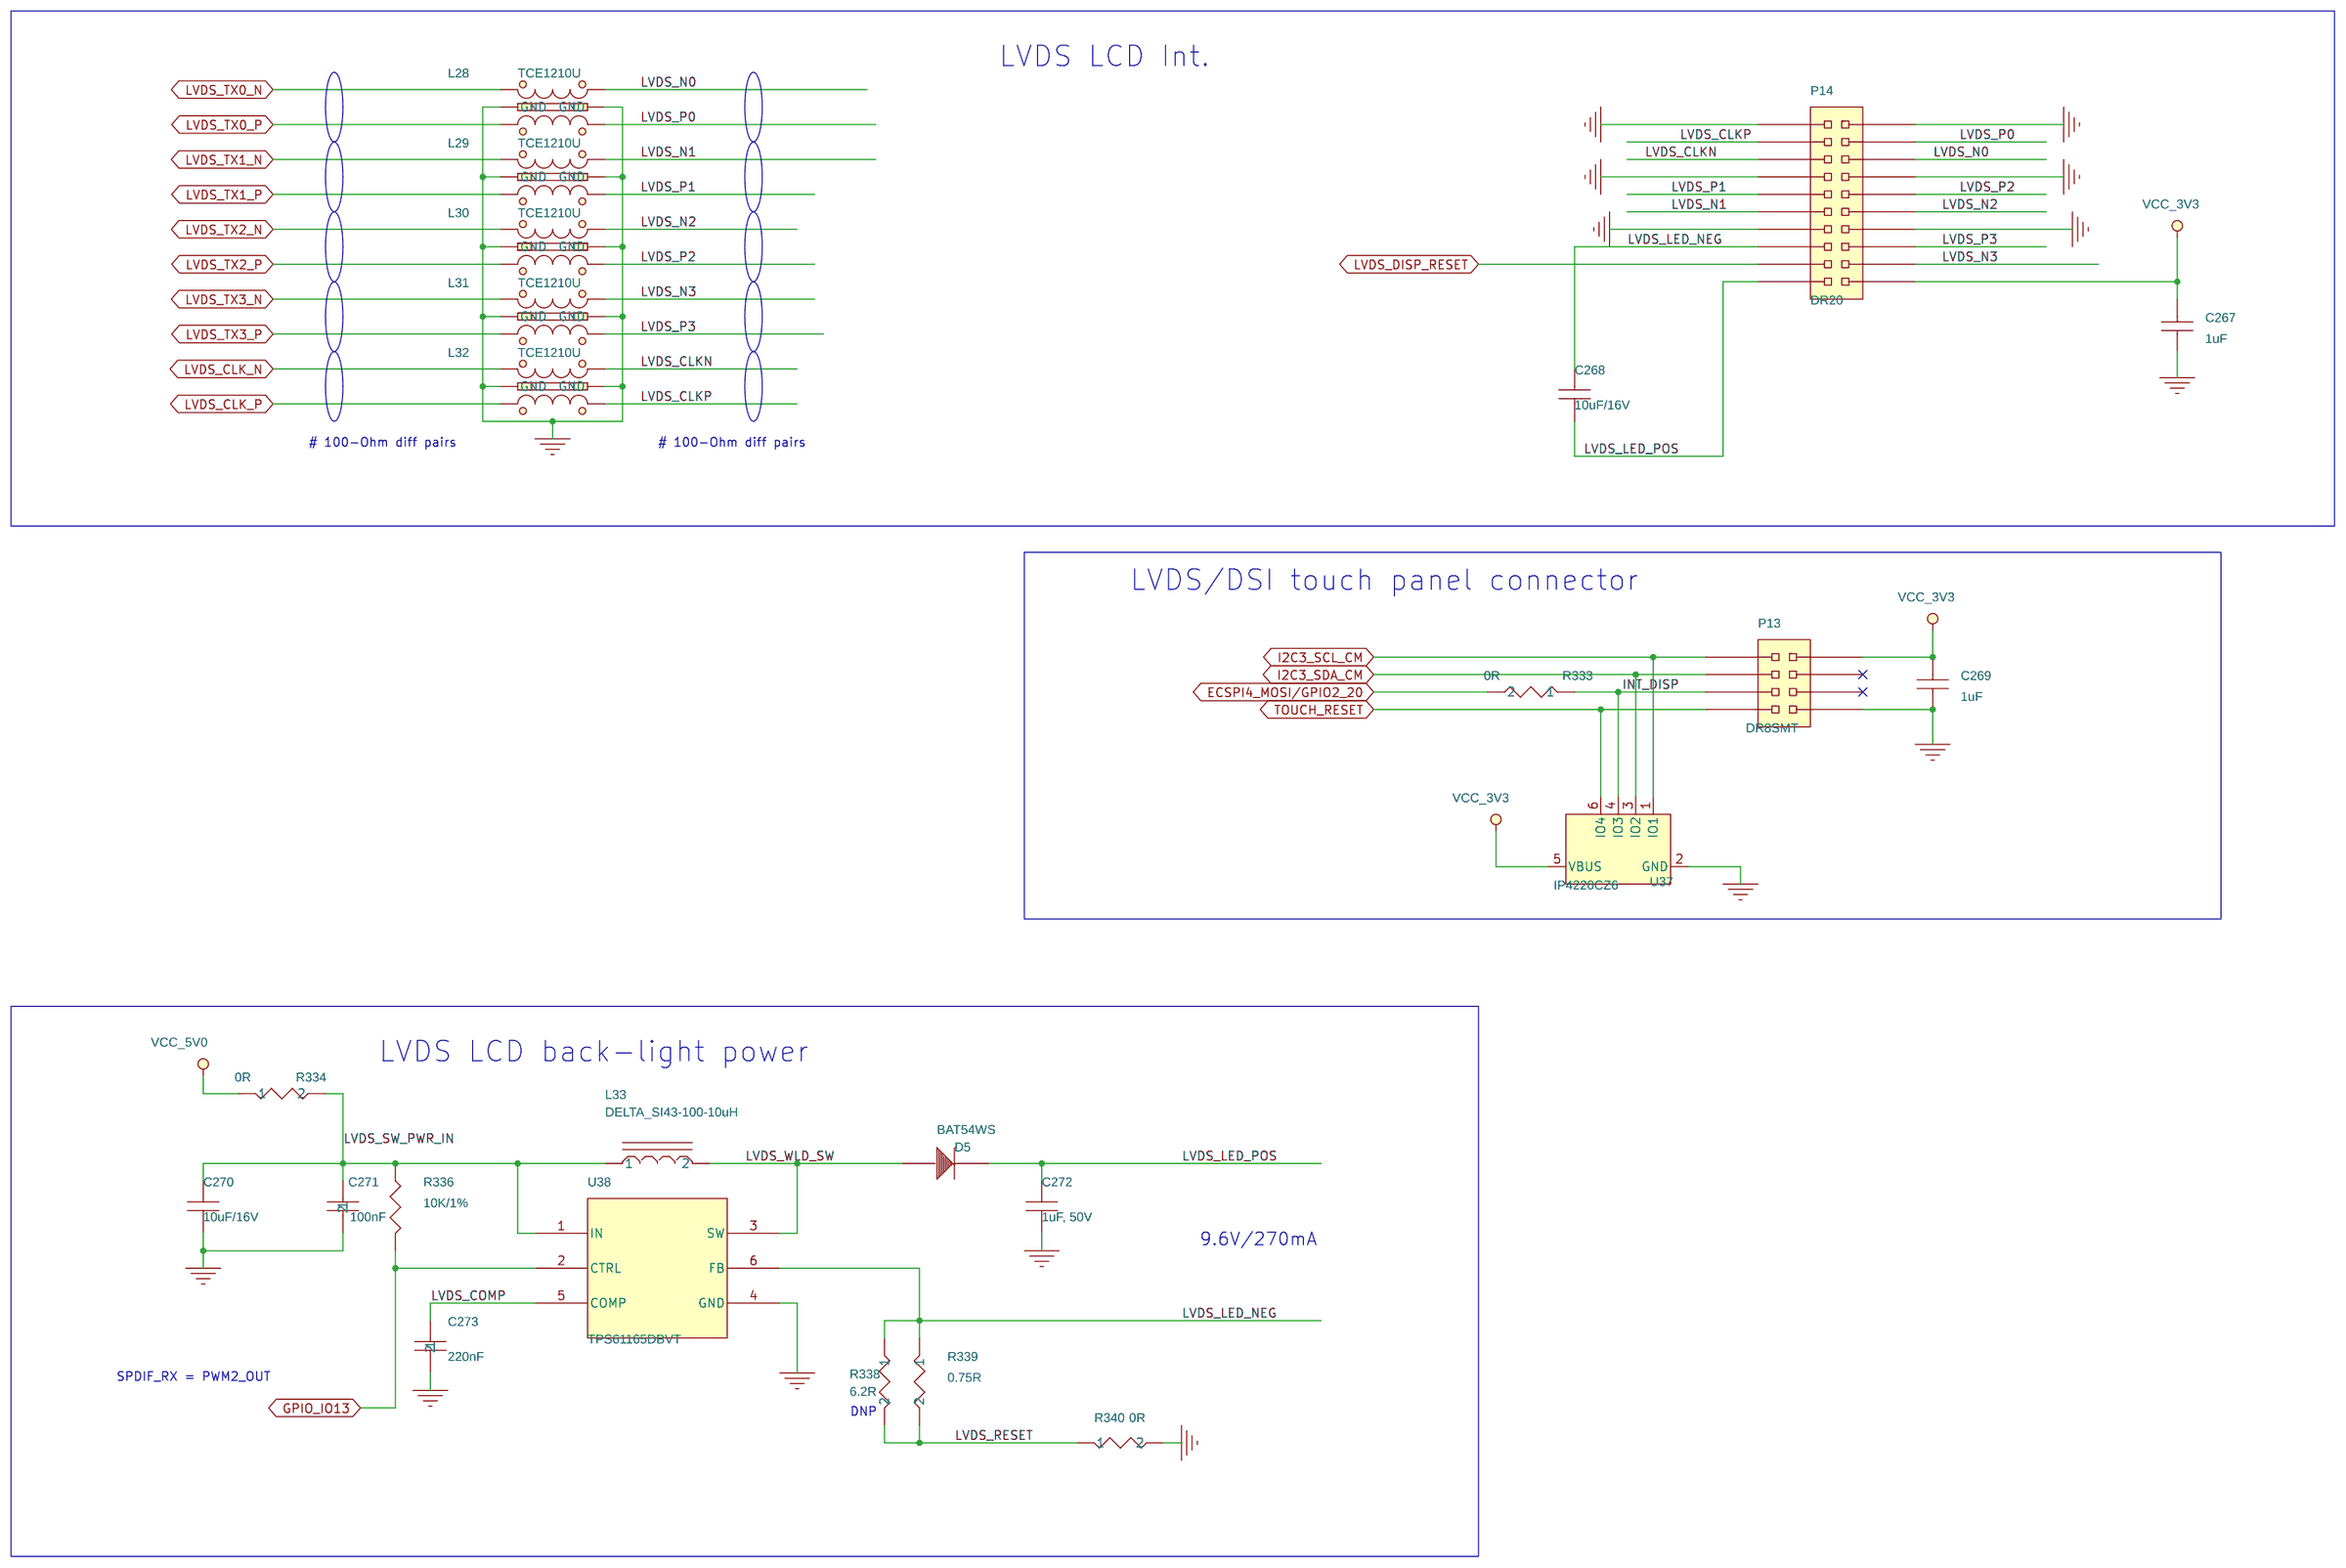
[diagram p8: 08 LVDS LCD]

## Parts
sheet 01 Index and Block Diagram
PCB1  PCB, SBEV-UCMIMX93, Rev 1.0
ZZ1  PARSER_VERSION_1.0
sheet 02 SOM Connectors
C200  10uF/10V  [0402]
C201  10uF/10V  [0402]
C202  100nF  [RC0402]
C203  10uF/10V  [0402]
C204  10uF/10V  [0402]
C205  10uF/10V  [0402]
C206  10uF/10V  [0402]
C207  100nF  [RC0402]
C208  100nF  [RC0402]
C209  100nF  [RC0402]
C210  100nF  [RC0402]
C211  100nF  [RC0402]
C212  100nF  [RC0402]
C213  100nF  [RC0402]
C214  100nF  [RC0402]
C215  100nF  [RC0402]
C216  100nF  [RC0402]
C217  100nF  [RC0402]
C218  100nF  [RC0402]
E3  HDR1X2  [1X2THHDR]
E4  HDR1X2  [1X2THHDR]
P1  Hirose DF40C-100DP-0.4V (1.5mm / 3.0mm stacking heights)  [B2B04M2X50P]
P2  Hirose DF40C-100DP-0.4V (1.5mm / 3.0mm stacking heights)  [B2B04M2X50P]
R237  0R  [RC0402]
R238  0R  [RC0402]
R239  1k, 1%  [RC0402]
R240  6.04k,1%  [RC0402]
SW2  PushB  [TACTSW6x6SM]
SW3  PushB  [TACTSW6x6SM]
SW4  PushB  [TACTSW6x6SM]
TP1  TESTPOINT  [TESTPOINT]
TP6  TESTPOINT SMT  [TESTPOINT]
TP7  TESTPOINT SMT  [TESTPOINT]
TP8  TESTPOINT SMT  [TESTPOINT]
TP9  TESTPOINT SMT  [TESTPOINT]
TP10  TESTPOINT SMT  [TESTPOINT]
TP11  TESTPOINT SMT  [TESTPOINT]
TP12  TESTPOINT SMT  [TESTPOINT]
sheet 03 DC INP, Discharge
C219  100nF  [RC0402]
C220  10uF/63V  [C1210H2_5]
C221  10uF/63V  [C1210H2_5]
C222  1uF,50V,0603  [RC0603]
D1  TVS diode ,22V,1500W  [DO-214AB]
DS2  LED-YELLOW  [LED-1206]
FB5  30 Ohm@5A  [FB0603]
FB6  30 Ohm@5A  [FB0603]
J1  Power Jack 10A  [PJ-0810-TH]
Q1  Si7413DN  [Powerpak1212-8]
Q11  BSH103BK  [SOT23]
Q12  BSH103BK  [SOT23]
Q13  BSH103BK  [SOT23]
Q14  BSH103BK  [SOT23]
Q15  BSH103BK  [SOT23]
R241  1.5K/1%  [RC0402]
R242  10k  [RC0402]
R243  10R,5%,0603  [RC0603]
R244  10R,5%,0603  [RC0603]
R245  10R,5%,0603  [RC0603]
R246  10R,5%,0603  [RC0603]
R247  10R,5%,0603  [RC0603]
R248  10R,5%,0603  [RC0603]
R249  10R,5%,0603  [RC0603]
R250  10R,5%,0603  [RC0603]
R251  10R,5%,0603  [RC0603]
R252  10R,5%,0603  [RC0603]
R253  30k,1%  [RC0402]
R254  562k,1%  [RC0402]
R255  301k,1%  [RC0402]
SW1  SW KEY-SPST
sheet 04 Ethernet  connectors
C223  10uF ,6.3V,0603  [RC0603]
C224  100nF  [RC0402]
C225  100nF  [RC0402]
C226  10uF ,6.3V,0603  [RC0603]
C227  100nF  [RC0402]
C228  100nF  [RC0402]
P5  1Gbit_RJ45  [DUSBRJ-1G]
P6  1Gbit_RJ45  [DUSBRJ-1G]
R256  475R/1%  [RC0402]
R257  475R/1%  [RC0402]
R258  0R  [RC0402]
R259  475R/1%  [RC0402]
R260  0R  [RC0402]
R261  475R/1%  [RC0402]
R262  0R  [RC0402]
sheet 06 Codec
C92  15pF,50V,NPO  [RC0402]
C93  1uF,16V,X5R/X7R  [RC0402]
C94  10pF  [RC0402]
C95  10pF  [RC0402]
C99  2.2uF,10V,X5R  [RC0402]
C100  100nF  [RC0402]
C101  2.2uF,10V,X5R  [RC0402]
C102  2.2uF,10V,X5R  [RC0402]
C103  4.7uF,10V  [RC0402]
C104  4.7uF,10V  [RC0402]
C105  100nF  [RC0402]
C111  4.7uF,10V  [RC0402]
C112  100nF  [RC0402]
C113  4.7uF,10V  [RC0402]
C114  100nF  [RC0402]
C116  4.7uF,10V  [RC0402]
C117  4.7uF,10V  [RC0402]
C118  4.7uF,10V  [RC0402]
C119  4.7uF,10V  [RC0402]
C120  4.7uF,10V  [RC0402]
C127  22uF,25V,X5R/X7R  [C0805]
C189  15pF,50V,NPO  [RC0402]
C190  1uF,16V,X5R/X7R  [RC0402]
C194  220pF  [RC0603]
C199  220pF  [RC0603]
J5  AUDIO JACK 3.5mm  [AJ35-4P-SW-SM]
J6  AUDIO JACK 3.5mm  [AJ35-4P-SW-SM]
L7  FB, 120R 500mA  [FB0402]
L8  FB, 120R 500mA  [FB0402]
L9  FB, 120R 500mA  [FB0402]
L17  FB, 120R 500mA  [FB0402]
L18  FB, 120R 500mA  [FB0402]
R104  20.5R,1%,0402  [RC0402]
R105  562K  [RC0402]
R110  20.5R,1%,0402  [RC0402]
R111  0R  [RC0402]
R112  0R  [RC0402]
R114  0R  [RC0402]
R122  0R  [RC0402]
R123  0R  [RC0402]
R124  10K/1%  [RC0402]
R125  10K/1%  [RC0402]
R214  10K/1%  [RC0402]
R215  10K/1%  [RC0402]
R216  0R  [RC0402]
R217  100K  [RC0402]
R218  10K/1%  [RC0402]
TP3  TESTPOINT SMT  [TESTPOINT]
TP4  TESTPOINT SMT  [TESTPOINT]
TP5  TESTPOINT SMT  [TESTPOINT]
U16  WM8962BECSN/R  [BGA49_0P5_3P62X4]
X4  24.000MHz (10PPM)  [OSC3225]
sheet 07 MIPI-DSI LCD
C262  1uF  [RC0402]
C263  10uF,25V  [RC0603]
C264  10uF/16V  [RC0603]
C265  100nF  [RC0402]
C266  1uF, 50V  [RC0603]
D3  BAT54WS  [SOD-323]
D4  ZENER 24V  [SOD-123]
L22  TCE1210U  [EMI1012-ESD]
L23  TCE1210U  [EMI1012-ESD]
L24  TCE1210U  [EMI1012-ESD]
L25  TCE1210U  [EMI1012-ESD]
L26  TCE1210U  [EMI1012-ESD]
L27  DELTA_SI43-100-10uH  [IND4x4x2_5]
P12  DR20  [2X12THHDR]
R326  2.2K  [RC0402]
R327  0R  [RC0402]
R328  10K/1%  [RC0402]
R329  0R  [RC0402]
R330  0R  [RC0402]
R331  6.2R  [RC0402]
R332  0R  [RC0402]
U36  YB9285  [SOT23-6L]
sheet 08 LVDS LCD
C267  1uF  [RC0402]
C268  10uF/16V  [RC0603]
C269  1uF  [RC0402]
C270  10uF/16V  [RC0603]
C271  100nF  [RC0402]
C272  1uF, 50V  [RC0603]
C273  220nF  [RC0402]
D5  BAT54WS  [SOD-323]
L28  TCE1210U  [EMI1012-ESD]
L29  TCE1210U  [EMI1012-ESD]
L30  TCE1210U  [EMI1012-ESD]
L31  TCE1210U  [EMI1012-ESD]
L32  TCE1210U  [EMI1012-ESD]
L33  DELTA_SI43-100-10uH  [IND4x4x2_5]
P13  DR8SMT  [2X4SMHDR]
P14  DR20  [2X12THHDR]
R333  0R  [RC0402]
R334  0R  [RC1206]
R336  10K/1%  [RC0402]
R338  6.2R  [RC0402]
R339  0.75R  [RC0402]
R340  0R  [RC0402]
U37  IP4220CZ6  [SOT23-6L]
U38  TPS61165DBVT  [SOT23-6]
sheet 09  SPDIF,CAN, CSI,MISC
C242  10uF/10V  [RC0402]
C243  100nF  [RC0402]
C244  100nF  [RC0402]
C245  10uF/10V  [RC0402]
C246  100nF  [RC0402]
C248  100nF  [RC0402]
C249  10nF  [RC0402]
C250  100pF  [RC0402]
C251  100nF  [RC0402]
C252  100nF  [RC0402]
C253  100nF  [RC0402]
C254  100nF  [RC0402]
C255  100nF  [RC0402]
C256  100nF  [RC0402]
C257  100nF  [RC0402]
C258  100nF  [RC0402]
C259  100nF  [RC0402]
C260  100nF  [RC0402]
C261  100nF  [RC0402]
C315  100nF  [RC0402]
DS4  LED-GREEN  [LED-1206]
DS5  LED-YELLOW  [LED-1206]
E6  HDR1X2  [1X2THHDR]
E7  HDR1X2  [1X2THHDR]
E12  HDR1X2  [1X2THHDR]
J4  CON50A
P9  DR8SMT  [2X4SMHDR]
P10  DR8SMT  [2X4SMHDR]
P15  DR8SMT  [2X4SMHDR]
P16  DR8SMT  [2X4SMHDR]
P17  DR8SMT  [2X4SMHDR]
P18  DR10SM  [2X5SMHDR]
P19  DR8SMT  [2X4SMHDR]
P20  DR8SMT  [2X4SMHDR]
P22  DR8SMT  [2X4SMHDR]
Q16  NTZD3154NT  [SOT-563-6]  (sections A,B)
Q17  P-MOS, 1.5A, 8V  [SOT23]
Q18  0.5A,20V,Vgs max 6V  [SOT-563-6]
R285  120R  [RC0402]
R289  0R  [RC0402]
R293  10K  [RC0402]
R294  100R/1%  [RC0402]
R295  220R  [RC0402]
R296  0R  [RC0402]
R297  200R  [RC0402]
R298  200R  [RC0402]
R299  10K/1%  [RC0402]
R300  0R  [RC0402]
R301  10K/1%  [RC0402]
R302  10K  [RC0402]
R303  10K  [RC0402]
R304  0R  [RC0402]
R305  0R  [RC0402]
R306  0R  [RC0402]
R307  10K/1%  [RC0402]
R308  0R  [RC0402]
R309  0R  [RC0402]
R310  0R  [RC0402]
R311  0R  [RC0402]
R312  1K/1%  [RC0402]
R313  0R  [RC0402]
R314  1K/1%  [RC0402]
R315  0R  [RC0402]
R316  1K/1%  [RC0402]
R317  0R  [RC0402]
R318  0R  [RC0402]
R319  0R  [RC0402]
R320  0R  [RC0402]
R321  0R  [RC0402]
R322  0R  [RC0402]
R323  0R  [RC0402]
R324  0R  [RC0402]
R325  0R  [RC0402]
RN1  10K/8P4R  [RESNET8P0805]
U33  ATA6563  [SOI8-150]
U35  PCA9555  [QFN4x4-24]
sheet 11 USB
C229  1uF,16V  [RC0402]
C230  10uF  [C0603-08]
C231  100nF  [RC0402]
C232  100nF  [RC0402]
C233  10uF  [C0603-08]
C234  1uF,16V  [RC0402]
C235  100nF  [RC0402]
C236  1uF,16V  [RC0402]
C237  22uF/25V  [C0805]
C238  100nF  [RC0402]
C239  1uF,16V  [RC0402]
C240  22uF/25V  [C0805]
C294  10uF  [C0603-08]
C316  1uF,16V  [RC0402]
E11  HDR1X2  [1X2THHDR]
J2  USBConn_typeA  [USB-A-SM]
J3  USBConn_typeA  [USB-A-SM]
L19  TCE1210U  [EMI1012-ESD]
L20  TCE1210U  [EMI1012-ESD]
L21  TCE1210U  [EMI1012-ESD]
P21  microUSB  TYPE-AB  [MICRO-USB-AB-RA-SM]
R263  0R  [RC0402]
R264  1K  [RC0402]
R265  1K  [RC0402]
R266  0R  [RC0402]
R267  1K  [RC0402]
R268  0R  [RC0402]
R269  14.7K,1%,0402  [RC0402]
R270  10K/1%  [RC0402]
R271  10k  [RC0402]
R272  14.7K,1%,0402  [RC0402]
R273  10k  [RC0402]
R274  10k  [RC0402]
R275  0R  [RC0402]
R276  0R  [RC0402]
R277  0R  [RC0402]
R278  200K/1%  [RC0402]
R279  10k  [RC0402]
R280  0R  [RC0402]
R281  0R  [RC0402]
R282  10K/1%  [RC0402]
R283  10k  [RC0402]
R284  200K/1%  [RC0402]
U27  USB2.0 mux  [MO-255U1418E]
U28  NC7SB3157  [SC70-6]
U29  RT9703,3A Power switch  [SO8-150]
U30  NC7SB3157  [SC70-6]
U31  USB2.0 mux  [MO-255U1418E]
U32  RT9703,3A Power switch  [SO8-150]

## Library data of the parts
PCB1 = PCB,_EM-X270_Rev_1_0.1: CLABCONF0: =SBEV-UCMIMX93; P/N: 188C04680
ZZ1 = PARSER_VERSION_1_1.0: CLABCONF0: DNP
C200 C245 = 10uF_10V_20%_0402: CLABCONF0: =SBEV-UCMIMX93
C201 = 10uF,6.3V,0603,20%X5R_1: CLABCONF0: =SBEV-UCMIMX93; P/N: 151B10600S
C105 C202 C224 C252 C271 = 100nF,_10V,_X7R,_10%,_0402_1: CLABCONF0: =SBEV-UCMIMX93
C203 C242 = 10uF_10V_20%_0402_1: CLABCONF0: =SBEV-UCMIMX93
C204 = 10uF,6.3V,0603,20%X5R_3: CLABCONF0: =SBEV-UCMIMX93; P/N: 151B10600S
C205 = 10uF,6.3V,0603,20%X5R_2: CLABCONF0: =SBEV-UCMIMX93; P/N: 151B10600S
C206 = 10uF,6.3V,0603,20%X5R: CLABCONF0: =SBEV-UCMIMX93; P/N: 151B10600S
C100 C207 C228 C254 = 100nF,_10V,_X7R,_10%,_0402_3: CLABCONF0: =SBEV-UCMIMX93
C208 C251 = 100nF,_10V,_X7R,_10%,_0402_4: CLABCONF0: =SBEV-UCMIMX93
C209 C315 = 100nF,_10V,_X7R,_10%,_0402_9: CLABCONF0: =SBEV-UCMIMX93
C114 C210 C227 C260 = 100nF,_10V,_X7R,_10%,_0402_2: CLABCONF0: =SBEV-UCMIMX93
C211 C256 = 100nF,_10V,_X7R,_10%,_0402_5: CLABCONF0: =SBEV-UCMIMX93
C112 C212 C219 C225 C258 C265 = 100nF,_10V,_X7R,_10%,_0402: CLABCONF0: =SBEV-UCMIMX93
C213 C261 = 100nF,_10V,_X7R,_10%,_0402_10: CLABCONF0: =SBEV-UCMIMX93
C214 C248 = 100nF,_10V,_X7R,_10%,_0402_7: CLABCONF0: =SBEV-UCMIMX93
C215 C257 = 100nF,_10V,_X7R,_10%,_0402_11: CLABCONF0: =SBEV-UCMIMX93
C216 C259 = 100nF,_10V,_X7R,_10%,_0402_6: CLABCONF0: =SBEV-UCMIMX93
C217 C253 = 100nF,_10V,_X7R,_10%,_0402_8: CLABCONF0: =SBEV-UCMIMX93
C218 C246 = 100nF,_10V,_X7R,_10%,_0402_12: CLABCONF0: =SBEV-UCMIMX93
E3 E7 = HDR_1x2_100MIL_TH_JUMPER_1: CLABCONF0: =SBEV-UCMIMX93
E4 E6 E11 = HDR_1x2_100MIL_TH_JUMPER: CLABCONF0: =SBEV-UCMIMX93
P1 = Hirose_DF40C-100DP-0_0.4V: CLABCONF0: =SBEV-UCMIMX93; P/N: 182K10004S
P2 = Hirose_DF40C-100DP-0_1.4V: CLABCONF0: =SBEV-UCMIMX93; P/N: 182K10004S
R237 = 0R,_0402_0_1: CLABCONF0: =SBEV-UCMIMX93; P/N: 161C00005S
R238 = 0R,_0402_0: CLABCONF0: =SBEV-UCMIMX93; P/N: 161C00005S
R239 R264 R265 R267 = RESISTOR: CLABCONF0: =SBEV-UCMIMX93; P/N: 161C10011S
R240 = RESISTOR: CLABCONF0: =SBEV-UCMIMX93; P/N: 161C60411S; Part Name: Res., 6.04K, 1%, 0402, 1/16W
SW2-SW4 = TACT_SW_6x6mm_SMT: CLABCONF0: =SBEV-UCMIMX93
TP1 = TESTPOINT: CLABCONF0: DNP; P/N: TESTPOINT_SMT
TP3-TP12 = TESTPOINT: CLABCONF0: DNP; P/N: 188Z01370S
C220 C221 = 22uF_25V: CLABCONF0: =SBEV-UCMIMX93; P/N: 151E10680S
C222 = CAP_NP: CLABCONF0: =SBEV-UCMIMX93; P/N: 151D10510S; Part Name: Cap., 1uF, 50V, X5R/X7R, 10%, 0603
D1 = Diode_,TVS_,15V,1500W_0: CLABCONF0: =SBEV-UCMIMX93; P/N: 132D10030S
DS2 DS5 = LED-RED_1206: CLABCONF0: =SBEV-UCMIMX93; P/N: 139A10110S
FB5 = Ferrite_bead_,_30_Ohm@5A_1: CLABCONF0: =SBEV-UCMIMX93
FB6 = Ferrite_bead_,_30_Ohm@5A: CLABCONF0: =SBEV-UCMIMX93
J1 = DC_Jack_,5.5_2.5,10A,20V: CLABCONF0: =SBEV-UCMIMX93
Q1 = Si7413DN: CLABCONF0: =SBEV-UCMIMX93
Q11-Q15 = MOSFET_N_SOT23: CLABCONF0: =SBEV-UCMIMX93; P/N: 131D10160S
R241 = 1.5K_1%,_0402: CLABCONF0: =SBEV-UCMIMX93
R242 R283 = 1M_,5%,_0402: CLABCONF0: =SBEV-UCMIMX93; P/N: 161C10021S
R243-R252 = RESISTOR: CLABCONF0: =SBEV-UCMIMX93; P/N: 161D10R05S; Part Name: Res., 10R, 5%, 0603
R253 = RESISTOR: CLABCONF0: =SBEV-UCMIMX93; P/N: 161C30021S; Part Name: Res., 30K, 1%, 0402, 1/16W
R254 = RESISTOR: CLABCONF0: =SBEV-UCMIMX93; P/N: 161C56231S; Part Name: Res., 562K, 1%, 0402, 1/16W
R255 = RESISTOR: CLABCONF0: =SBEV-UCMIMX93; P/N: 161C30131S; Part Name: Res., 301K, 1%, 0402, 1/16W
SW1 = SW_KEY-SPST: CLABCONF0: =SBEV-UCMIMX93; P/N: 170F10010
C223 = Cap.,10uF,6.3V,0603,X5R_1: CLABCONF0: =SBEV-UCMIMX93
C226 = Cap.,10uF,6.3V,0603,X5R: CLABCONF0: =SBEV-UCMIMX93
P5 P6 = Con_0.,1GBit_RJ45,_short: CLABCONF0: =SBEV-UCMIMX93
R256 = 475R_1%,_0402_3: CLABCONF0: =SBEV-UCMIMX93
R257 = 475R_1%,_0402_1: CLABCONF0: =SBEV-UCMIMX93
R258 R266 R319 R327 = 0R,_0402_1: CLABCONF0: =SBEV-UCMIMX93
R259 = 475R_1%,_0402_2: CLABCONF0: =SBEV-UCMIMX93
R260 R318 = 0R,_0402_1_1: CLABCONF0: =SBEV-UCMIMX93
R261 = 475R_1%,_0402: CLABCONF0: =SBEV-UCMIMX93
R262 R304 = 0R,_0402_1_2: CLABCONF0: =SBEV-UCMIMX93
C92 C189 = CAP_NP: CLABCONF0: =SBEV-UCMIMX93; P/N: 151D15000S
C93 C190 = CAP_NP: CLABCONF0: =SBEV-UCMIMX93; P/N: 151C10500S
C94 = 10pF,50V,NPO,_5%,_0402: CLABCONF0: DNP
C95 = 10pF,50V,NPO,_5%,_0402_1: CLABCONF0: DNP
C99 C101 C102 = CAP_NP: CLABCONF0: =SBEV-UCMIMX93; P/N: 151B22500S
C103 = 15pF,_50V,_NPO,_5%,_0402_7: CLABCONF0: =SBEV-UCMIMX93; P/N: 151B47500S
C104 = 15pF,_50V,_NPO,_5%,_0402_8: CLABCONF0: =SBEV-UCMIMX93; P/N: 151B47500S
C111 = 15pF,_50V,_NPO,_5%,_0402_5: CLABCONF0: =SBEV-UCMIMX93; P/N: 151B47500S
C113 = 15pF,_50V,_NPO,_5%,_0402_4: CLABCONF0: =SBEV-UCMIMX93; P/N: 151B47500S
C116 = 15pF,_50V,_NPO,_5%,_0402_1: CLABCONF0: =SBEV-UCMIMX93; P/N: 151B47500S
C117 = 15pF,_50V,_NPO,_5%,_0402_2: CLABCONF0: =SBEV-UCMIMX93; P/N: 151B47500S
C118 = 15pF,_50V,_NPO,_5%,_0402_3: CLABCONF0: =SBEV-UCMIMX93; P/N: 151B47500S
C119 = 15pF,_50V,_NPO,_5%,_0402_6: CLABCONF0: =SBEV-UCMIMX93; P/N: 151B47500S
C120 = 15pF,_50V,_NPO,_5%,_0402: CLABCONF0: =SBEV-UCMIMX93; P/N: 151B47500S
C127 = CAP_NP: CLABCONF0: =SBEV-UCMIMX93; P/N: 151C22620S
C194 = 220pF,50V,NPO,0603_1: CLABCONF0: =SBEV-UCMIMX93
C199 = 220pF,50V,NPO,0603: CLABCONF0: =SBEV-UCMIMX93
J5 J6 = Audio_JACK,_STEREO+AUX+SW_3.5mm: CLABCONF0: =SBEV-UCMIMX93
L7 L17 L18 = Ferrit_330R-100Mhz,1.2A: CLABCONF0: =SBEV-UCMIMX93; P/N: 147D12102S
L8 L9 = Ferrit_330R-100Mhz,1.2A: CLABCONF0: DNP; P/N: 147D12102S
R104 R110 = RESISTOR: CLABCONF0: =SBEV-UCMIMX93; P/N: 161C20R51S
R105 = 10M,5%,0402,1_16W: CLABCONF0: DNP; P/N: 161C56231S
R111 = 0R,_0402_0_4: CLABCONF0: =SBEV-UCMIMX93
R112 = 0R,_0402_0_5: CLABCONF0: =SBEV-UCMIMX93
R114 = 0R,_0402_0: CLABCONF0: DNP
R122 = 0R,_0402_0_3: CLABCONF0: =SBEV-UCMIMX93
R123 = 0R,_0402_0_1: CLABCONF0: =SBEV-UCMIMX93
R124 = 10K,1%,0402,1_16W_0_2: CLABCONF0: DNP
R125 R293 = 10K,1%,0402,1_16W_0_3: CLABCONF0: =SBEV-UCMIMX93
R214 R282 R307 = 10K,1%,0402,1_16W_0_1: CLABCONF0: =SBEV-UCMIMX93
R215 = 10K,1%,0402,1_16W_0_4: CLABCONF0: =SBEV-UCMIMX93
R216 = 0R,_0402_0_2: CLABCONF0: =SBEV-UCMIMX93
R217 = 100K,_0402: CLABCONF0: =SBEV-UCMIMX93; P/N: 161C10031S
R218 R270 R303 R328 R336 = 10K,1%,0402,1_16W_0: CLABCONF0: =SBEV-UCMIMX93
U16 = WM8962_BGA_49P_A: IC AUDIO CODEC 24BIT DAC 2 CH ADC 1.8V BGA49; 3D_Mechanical_Footprint_File: ftp://fcl.am.freescale.net/ALLEGRO/step/BGA49_0P5_3P62X4.STEP; AGILE_PN: 315-80353; CAD_APPROVED: Yes; CLABCONF0: =SBEV-UCMIMX93; HEIGHT: 0.75MM; MFG_NAME01: WOLFSON MICROELECTRONICS; P/N: 117A10070S; ROHS: Yes; VOLTAGE: 1.8V
X4 = XTAL,24.000Mhz,100ppm,Ind,3x5mm: CLABCONF0: DNP; P/N: 141B24605I
C262 C267 C269 = 1uF,X5R,6.3V,0402: CLABCONF0: =SBEV-UCMIMX93
C263 = CAP_NP: CLABCONF0: =SBEV-UCMIMX93; P/N: 151C10611S; Part Name: Cap., 10uF, 25V, X5R/X7R, 20%, 0603
C264 C268 = 10uF,6.3V,0603,20%X5R: CLABCONF0: =SBEV-UCMIMX93
C266 C272 = 1uF,X5R,6.3V,0402: CLABCONF0: =SBEV-UCMIMX93; P/N: 151D10510S
D3 D5 = BAT54WS_0: CLABCONF0: =SBEV-UCMIMX93
D4 = ZENER_24V_500mW_SOD-123: CLABCONF0: DNP
L19-L26 L28-L32 = ESD_CHOKE_DIFFx2_10: CLABCONF0: =SBEV-UCMIMX93; P/N: 142D11801S
L27 L33 = INC_DELTA_SI43-100,_10uH: CLABCONF0: =SBEV-UCMIMX93; CLABCONF1: <null>
P12 P14 = HDR_2x12_100MIL_0: CLABCONF0: =SBEV-UCMIMX93; P/N: 190C02000S
R326 = 2.2K,5%,0402.1_16W: CLABCONF0: =SBEV-UCMIMX93
R277 R329 R333 = 0R,_0402: CLABCONF0: =SBEV-UCMIMX93
R330 = 2.2R,5%,0402,1_16W_1: CLABCONF0: =SBEV-UCMIMX93; P/N: 161C00005S
R331 = 2.2R,5%,0402,1_16W: CLABCONF0: =SBEV-UCMIMX93; P/N: 161C06R25S
R332 = 0R,_0402_2: CLABCONF0: DNP
U36 = AIC1647_0: CLABCONF0: =SBEV-UCMIMX93; P/N: 123C40000S
C270 = 10uF,6.3V,0603,20%X5R_1: CLABCONF0: =SBEV-UCMIMX93
C273 = 100nF,_10V,_X7R,_10%,_0402: CLABCONF0: =SBEV-UCMIMX93; P/N: 151C22400S
P9 P10 P13 P15-P17 P19 P20 P22 = HDR_2x7_100MIL_RA_TH_SHRD_0: CLABCONF0: =SBEV-UCMIMX93; P/N: 190C00801S
R334 = 0R,_1206: CLABCONF0: =SBEV-UCMIMX93
R338 = 2.2R,5%,0402,1_16W_1: CLABCONF0: DNP; P/N: 161C06R25S
R339 = 2.2R,5%,0402,1_16W: CLABCONF0: =SBEV-UCMIMX93; P/N: 161C0R751S
R340 = 2.2R,5%,0402,1_16W_2: CLABCONF0: =SBEV-UCMIMX93; P/N: 161C00005S
U37 = IP4220CZ6_0: CLABCONF0: =SBEV-UCMIMX93
U38 = TPS61165DBVT: CLABCONF0: =SBEV-UCMIMX93; P/N: 123C15100S
C243 C244 = 100nF,_10V,_X7R,_10%,_0402_0: CLABCONF0: =SBEV-UCMIMX93
C249 = 10nF,_25V,_X7R,_10%,_0402: CLABCONF0: =SBEV-UCMIMX93
C250 = 100pF,_50V,_NPO,_5%,_0402: CLABCONF0: =SBEV-UCMIMX93
C255 = 100nF,_10V,_X7R,_10%,_0402_13: CLABCONF0: =SBEV-UCMIMX93
DS4 = LED-GREEN_1206_2: CLABCONF0: =SBEV-UCMIMX93
E12 = HDR_1x2_100MIL_TH_JUMPER_2: CLABCONF0: =SBEV-UCMIMX93
J4 = CON50A: CLABCONF0: =SBEV-UCMIMX93; P/N: 182K05001S
P18 = HDR_2x5_100MIL_SMT: CLABCONF0: =SBEV-UCMIMX93
Q16 = N-MOSFET_Dual: CLABCONF0: =SBEV-UCMIMX93; P/N: 131D31540S
Q17 = P-MOS,_1.5A,_8V: CLABCONF0: DNP
Q18 = DUAL_N-MOSFET,_0.5A_20V: CLABCONF0: =SBEV-UCMIMX93
R285 = 0R,_0402_0_1: CLABCONF0: =SBEV-UCMIMX93; Group: Always; P/N: 161C12001S
R289 = 0R,_0402_1_17: CLABCONF0: DNP
R294 = 100R,1%,0402,1_16W: CLABCONF0: =SBEV-UCMIMX93
R295 = 220R,5%,0402,1_16W: CLABCONF0: =SBEV-UCMIMX93
R296 = 0R,_0402_1_15: CLABCONF0: =SBEV-UCMIMX93
R297 = 348R,1%,0402,1_16W: CLABCONF0: =SBEV-UCMIMX93; P/N: 161C20001S
R298 = 348R,1%,0402,1_16W_1: CLABCONF0: =SBEV-UCMIMX93; P/N: 161C20001S
R299 = 10K,1%,0402,1_16W_1: CLABCONF0: =SBEV-UCMIMX93
R300 = 0R,_0402_1_5: CLABCONF0: DNP
R301 = 10K,1%,0402,1_16W: CLABCONF0: =SBEV-UCMIMX93
R302 = 10K,1%,0402,1_16W_0_2: CLABCONF0: =SBEV-UCMIMX93
R305 = 0R,_0402_1_12: CLABCONF0: =SBEV-UCMIMX93
R306 = 0R,_0402_1_11: CLABCONF0: =SBEV-UCMIMX93
R308 = 0R,_0402_1_3: CLABCONF0: =SBEV-UCMIMX93
R309 = 0R,_0402_0: CLABCONF0: DNP; P/N: 161C00005S
R310 = 0R,_0402_1_10: CLABCONF0: =SBEV-UCMIMX93
R311 = 0R,_0402_1_7: CLABCONF0: =SBEV-UCMIMX93
R312 = 1K,1%,0402,1_16W_2: CLABCONF0: DNP; Group: CAN
R313 = 0R,_0402_1_4: CLABCONF0: =SBEV-UCMIMX93
R314 = 1K,1%,0402,1_16W_1: CLABCONF0: DNP; Group: CAN
R315 = 0R,_0402_1_16: CLABCONF0: =SBEV-UCMIMX93
R316 = 1K,1%,0402,1_16W: CLABCONF0: DNP; Group: CAN
R317 = 0R,_0402_1_19: CLABCONF0: =SBEV-UCMIMX93
R320 = 0R,_0402_1_8: CLABCONF0: =SBEV-UCMIMX93
R321 = 0R,_0402_1_18: CLABCONF0: =SBEV-UCMIMX93
R322 = 0R,_0402_1_13: CLABCONF0: =SBEV-UCMIMX93
R323 = 0R,_0402_1_6: CLABCONF0: =SBEV-UCMIMX93
R324 = 0R,_0402_1_14: CLABCONF0: =SBEV-UCMIMX93
R325 = 0R,_0402_1_9: CLABCONF0: =SBEV-UCMIMX93
RN1 = RN,10K,8P4R@0805: CLABCONF0: =SBEV-UCMIMX93
U33 = ATA6563: CLABCONF0: =SBEV-UCMIMX93; P/N: 116A00380S
U35 = PCA9555_1: CLABCONF0: =SBEV-UCMIMX93
C229 = 100nF,_10V,_X7R,_10%,_0402_1: CLABCONF0: =SBEV-UCMIMX93; P/N: 151C10500S
C230 C233 C294 = 10uF,6_0.3V,0603,20%X5R: CLABCONF0: =SBEV-UCMIMX93
C231 = 100nF,_10V,_X7R,_10%,_0402_7: CLABCONF0: =SBEV-UCMIMX93; Group: LAN2
C232 = 100nF,_10V,_X7R,_10%,_0402_5: CLABCONF0: =SBEV-UCMIMX93; Group: LAN2
C234 = 100nF,_10V,_X7R,_10%,_0402_2: CLABCONF0: =SBEV-UCMIMX93; P/N: 151C10500S
C235 = 100nF,_10V,_X7R,_10%,_0402_3: CLABCONF0: =SBEV-UCMIMX93; Group: LAN2
C236 = 100nF,_10V,_X7R,_10%,_0402_8: CLABCONF0: =SBEV-UCMIMX93; P/N: 151C10500S
C237 = 22uF,25V,_0805_1: CLABCONF0: =SBEV-UCMIMX93
C238 = 100nF,_10V,_X7R,_10%,_0402: CLABCONF0: =SBEV-UCMIMX93; Group: LAN2
C239 = 100nF,_10V,_X7R,_10%,_0402_6: CLABCONF0: =SBEV-UCMIMX93; P/N: 151C10500S
C240 = 22uF,25V,_0805: CLABCONF0: =SBEV-UCMIMX93
C316 = 100nF,_10V,_X7R,_10%,_0402_4: CLABCONF0: =SBEV-UCMIMX93; P/N: 151C10500S
J2 J3 = USB_Conn.,_Fem,_Type_A_,_TH,_RA: CLABCONF0: =SBEV-UCMIMX93
P21 = Conn.,_Micro-USB,_B-Type: CLABCONF0: =SBEV-UCMIMX93; P/N: 180K00501S
R263 = 0R,_0402_6: CLABCONF0: DNP
R268 = 0R,_0402_7: CLABCONF0: =SBEV-UCMIMX93
R269 R272 = RESISTOR: CLABCONF0: =SBEV-UCMIMX93; P/N: 161C14721S
R271 = 1M_,5%,_0402_1: CLABCONF0: =SBEV-UCMIMX93; P/N: 161C10021S
R273 = 1M_,5%,_0402_3: CLABCONF0: =SBEV-UCMIMX93; P/N: 161C10021S
R274 = 1M_,5%,_0402_4: CLABCONF0: =SBEV-UCMIMX93; P/N: 161C10021S
R275 = 0R,_0402_2: CLABCONF0: =SBEV-UCMIMX93
R276 = 0R,_0402_5: CLABCONF0: =SBEV-UCMIMX93
R278 = 100K,_1%,_0402,_1_16W_1: CLABCONF0: =SBEV-UCMIMX93; P/N: 161C20031S
R279 = 1M_,5%,_0402_2: CLABCONF0: DNP; P/N: 161C10021S
R280 = 0R,_0402_3: CLABCONF0: =SBEV-UCMIMX93
R281 = 0R,_0402_4: CLABCONF0: DNP
R284 = 100K,_1%,_0402,_1_16W: CLABCONF0: =SBEV-UCMIMX93; P/N: 161C20031S
U27 = USB2_0.0_mux: CLABCONF0: =SBEV-UCMIMX93; P/N: 116A72220S
U28 U30 = Bus_switch_2_1: CLABCONF0: =SBEV-UCMIMX93
U29 U32 = RT9703,3A_Power_switch+FLG: CLABCONF0: =SBEV-UCMIMX93; P/N: 124S10080S
U31 = USB2_0.0_mux_v2: CLABCONF0: =SBEV-UCMIMX93; P/N: 116A72220S

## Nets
1V8_L: C104.2 C105.1 C113.2 C120.2 L7.1 U16.C6(CPVDD) U16.D6(AVDD) U16.G2(DCVDD) U16.G4(PLLVDD)
3V3_EXP: C255.1 Q17.3(D) R296.1 U35.21(VDD)
5V0_L: C117.2 C118.2 C127.1 L8.1 L9.1 U16.A2(SPKVDD1) U16.C2(SPKVDD2)
GND: C92.1 C94.1 C95.1 C99.2 C101.2 C103.1 C104.1 C105.2 C111.2 C113.1 C114.2 C116.1 C117.1 C118.1 C119.1 C120.1 C127.2 C189.1 C194.1 C199.1 C200.1 C201.1 C202.2 C203.1 C204.1 C205.1 C206.1 C207.2 C208.2 C209.2 C210.2 C211.2 C212.2 C213.2 C214.2 C215.2 C216.2 C217.2 C218.2 C220.2 C221.2 C222.2 C223.2 C224.2 C225.2 C226.2 C227.2 C228.2 C229.1 C230.2 C231.1 C232.1 C233.2 C234.1 C235.1 C236.1 C237.2 C238.1 C239.1 C240.2 C242.2 C243.2 C244.1 C245.2 C246.2 C248.2 C250.2 C251.2 C252.2 C253.2 C254.2 C255.2 C256.2 C257.2 C258.2 C259.2 C260.2 C261.2 C262.1 C264.2 C265.2 C266.2 C267.1 C269.1 C270.2 C271.2 C272.2 C273.2 C294.2 C315.2 C316.1 D1.ANODE DS2.CATHODE E11.2 J1.2(R) J1.SH1 J1.SH2 J1.SH3 J1.SH4 J2.4(GND) J2.5(SHELL_1) J2.6(SHELL_2) J3.4(GND) J3.5(SHELL_1) J3.6(SHELL_2) J4.1 J4.2 J4.7 J4.8 J4.13 J4.25 J4.26 J4.31 J4.32 J4.37 J4.38 J4.43 J5.1(COM) J6.1(COM) L19.5(GND) L19.6(GND) L20.5(GND) L20.6(GND) L21.5(GND) L21.6(GND) L22.5(GND) L22.6(GND) L23.5(GND) L23.6(GND) L24.5(GND) L24.6(GND) L25.5(GND) L25.6(GND) L26.5(GND) L26.6(GND) L28.5(GND) L28.6(GND) L29.5(GND) L29.6(GND) L30.5(GND) L30.6(GND) L31.5(GND) L31.6(GND) L32.5(GND) L32.6(GND) P1.4 P1.10 P1.20 P1.40 P1.54 P1.64 P1.78 P1.88 P2.10 P2.16 P2.22 P2.28 P2.34 P2.40 P2.46 P2.54 P2.72 P2.82 P5.S1(SHIELD) P5.S2(SHIELD) P6.S1(SHIELD) P6.S2(SHIELD) P9.8 P10.8 P12.1 P12.2 P12.7 P12.8 P12.13 P12.14 P13.8 P14.1 P14.2 P14.7 P14.8 P14.13 P14.14 P15.8 P16.8 P17.8 P18.10 P19.8 P20.8 P21.5(GND) P21.6(SHIELD1) P21.7(SHIELD2) P21.8(SHIELD3) P21.9(SHIELD4) P22.8 Q11.2(SOURCE) Q12.2(SOURCE) Q13.2(SOURCE) Q14.2(SOURCE) Q15.2(SOURCE) Q16.1(S) Q16.4(S) Q18.1(S1) Q18.4(S2) R104.2 R110.2 R111.2 R214.2 R215.2 R217.2 R255.2 R256.2 R257.2 R269.2 R270.1 R272.2 R277.1 R278.2 R279.1 R280.2 R282.1 R284.2 R293.1 R295.2 R301.2 R302.1 R303.1 R326.2 R330.2 R340.2 RN1.2(RB1) RN1.3(RC1) RN1.4(RD1) SW1.1 SW3.1 SW3.3 SW4.1 SW4.3 U16.B1(SPKGND1) U16.C1(SPKGND2) U16.C7(CPGND) U16.D7(AGND) U16.F2(CIFMODE) U16.F3(DGND) U16.G5(PLLGND) U27.4(GND) U28.2(GND) U29.4(GND) U30.2(GND) U31.4(GND) U32.4(GND) U33.2(GND) U35.9(VSS) U35.25(CPAD) U36.2(GND) U37.2(GND) U38.4(GND) X4.2 X4.4 ; also on sheet 10 11 12 13
VBUS_USB_A: C229.2 C230.1 C237.1 J3.1(VBUS) R263.1 R265.1 U29.2(Vout) U29.3(Vout)
VBUS_USB_B: C240.1 C294.1 C316.2 J2.1(VBUS) R281.1 U32.2(Vout) U32.3(Vout)
VCC_1V8: C251.1 C253.1 C258.1 C315.1 J4.14 J4.50 L7.2 P9.1 P22.1 R247.1 R248.1 ; also on sheet 10 11 12 13
VCC_3V3: C114.1 C116.2 C119.2 C231.2 C238.2 C242.1 C243.1 C248.1 C252.1 C254.1 C256.1 C257.1 C259.1 C260.1 C261.1 C262.2 C267.2 C269.2 DS4.ANODE DS5.ANODE E3.2 J4.19 J4.49 L8.2 P10.1 P12.20 P13.2 P14.20 P15.1 P16.1 P18.1 P19.1 P20.1 Q17.2(S) R124.1 R125.1 R218.1 R245.1 R246.1 R260.1 R262.1 R273.2 R274.2 R283.2 R296.2 R299.2 R307.1 R312.1 R314.1 R316.1 R327.1 SW2.1 SW2.3 U16.A3(MICVDD) U16.G3(DBVDD) U27.9(VCC) U31.9(VCC) U33.5(VIO) U37.5(VBUS) ; also on sheet 10 11 12 13
VCC_5V0: C232.2 C235.2 C236.2 C239.2 C244.2 C245.1 C246.1 L9.2 P17.1 R249.1 R250.1 R334.1 U28.5(VCC) U29.6(Vin) U29.7(Vin) U30.5(VCC) U32.6(Vin) U32.7(Vin) U33.3(VCC) ; also on sheet 13
VCC_RTC: P1.93 ; also on sheet 13
ADC_IN0: P2.89 P9.2
ADC_IN1: P2.91 P9.4
ADC_IN2: P2.93 P9.6
ADC_IN3: P2.95 P9.3
ALT_BOOT: P1.90 R239.1
AUD_SCL: R123.1 U16.F1(SCLK)
AUD_SDA: R122.1 U16.E2(SDA)
BOOT_MODE0: E6.2 P1.75
BOOT_MODE1: E6.1 P1.80
BOOT_MODE2: E7.2 P1.82
BOOT_MODE3: E7.1 P1.58
C_VOTN: C101.1 U16.A7(CPVOUTN)
C_VOTP: C99.1 U16.A6(CPVOUTP)
CAN1_H: P17.2 R285.2 U33.7(CANH)
CAN1_L: E12.1 P17.6 R289.2 U33.6(CANL)
CAN_STBY: R293.2 U33.8(STBY)
CAN_T: E12.2 R285.1 R289.1
CARRIER_3V3_GPIO0_0: R304.2 U35.1(I/O0.0)
CARRIER_3V3_GPIO0_1: R305.2 U35.2(I/O0.1)
CARRIER_3V3_GPIO0_2: R306.2 U35.3(I/O0.2)
CARRIER_3V3_GPIO0_3: R308.2 U35.4(I/O0.3)
CARRIER_3V3_GPIO0_4: R310.2 U35.5(I/O0.4)
CARRIER_3V3_GPIO0_5: R311.2 U35.6(I/O0.5)
CARRIER_3V3_GPIO0_6: R313.2 U35.7(I/O0.6)
CARRIER_3V3_GPIO0_7: R315.2 U35.8(I/O0.7)
CARRIER_3V3_GPIO1_0: R317.2 U35.10(I/O1.0)
CARRIER_3V3_GPIO1_1: R318.2 U35.11(I/O1.1)
CARRIER_3V3_GPIO1_2: R319.2 U35.12(I/O1.2)
CARRIER_3V3_GPIO1_3: R320.2 U35.13(I/O1.3)
CARRIER_3V3_GPIO1_4: R321.2 U35.14(I/O1.4)
CARRIER_3V3_GPIO1_5: R322.2 U35.15(I/O1.5)
CARRIER_3V3_GPIO1_6: R323.2 U35.16(I/O1.6)
CARRIER_3V3_GPIO1_7: R324.2 U35.17(I/O1.7)
CLKOUT2: TP5.1 U16.E4(CLKOUT2/GPIO2)
CLKOUT5: TP3.1 U16.G6(CLKOUT5)
CODEC_INT: R114.2 R125.2 U16.E3(~{CS}/GPIO6)
CPCA: C102.1 U16.B6(CPCA)
CPCB: C102.2 U16.B7(CPCB)
CSI1_CONTR: J4.20 R305.1
CSI1_FLASH_OUT: J4.24 R319.1
CSI1_PWR_DWN: J4.21 R317.1
CSI1_RST: J4.23 R318.1
CSI1_TRG: J4.22 R320.1
CSI_CLK_N: J4.6 P2.30
CSI_CLK_P: J4.4 P2.32
CSI_D0_N: J4.5 P2.31
CSI_D0_P: J4.3 P2.33
CSI_D1_N: J4.12 P2.35
CSI_D1_P: J4.10 P2.37
DC_FLT: C219.1 FB5.2 FB6.2 Q1.1(S) Q1.2(S) Q1.3(S) R241.2 R242.2
DC_IN_LED: DS2.ANODE R241.1
DC_JACK: C222.1 D1.CATHODE FB5.1 FB6.1 J1.1(CENTRAL)
DISCH_ON_H: Q11.1(GATE) Q12.1(GATE) Q13.1(GATE) Q14.1(GATE) Q15.1(GATE) R254.2 R255.1
DISCH_ONH: R253.2 R254.1 SW1.2
DS3_G#: Q18.3(D2) R298.1
DS3_R#: Q18.6(D1) R297.1
DS4_G: DS4.CATHODE R297.2
DS5_Y: DS5.CATHODE R298.2
DSI1_CN: L24.1 P12.5
DSI1_CP: L24.2 P12.3
DSI1_N0: L22.1 P12.6
DSI1_N1: L23.1 P12.11
DSI1_N2: L25.1 P12.12
DSI1_N3: L26.1 P12.18
DSI1_P0: L22.2 P12.4
DSI1_P1: L23.2 P12.9
DSI1_P2: L25.2 P12.10
DSI1_P3: L26.2 P12.16
DSI_BCKLIGHT_FB: D4.2(ANODE) R329.2 U36.3(FB)
DSI_BCKLIGHT_IN: C264.1 C265.1 L27.1 R327.2 R328.1 U36.6(IN)
DSI_CLK_N: L24.4 P2.21
DSI_CLK_P: L24.3 P2.23
DSI_D0_N: L22.4 P2.1
DSI_D0_P: L22.3 P2.3
DSI_D1_N: L23.4 P2.15
DSI_D1_P: L23.3 P2.17
DSI_D2_N: L25.4 P2.5
DSI_D2_P: L25.3 P2.7
DSI_D3_N: L26.4 P2.11
DSI_D3_P: L26.3 P2.13
DSI_DISP_RESET: P12.17 R310.1 R326.1
DSI_LED_A: C263.2 C266.1 D3.CATHODE D4.1(CATHODE) P12.19 U36.5(OVP)
DSI_LED_EN: R328.2 R332.2 U36.4(EN/PWM)
DSI_LED_K: C263.1 P12.15 R329.1 R331.1
DSI_WLD_RES: R330.1 R331.2
DSI_WLD_SW: D3.ANODE L27.2 U36.1(LX)
ECSPI3_MISO/UART7_RX: P1.41 P15.2
ECSPI3_MOSI: P1.35 P15.3
ECSPI3_SCLK: P1.37 P15.5
ECSPI3_SS0/UART7_TX: P1.39 P15.4
ECSPI4_MISO/GPIO2_19: P1.59 R332.1
ECSPI4_MOSI/GPIO2_20: P1.61 R333.2
ECSPI4_SCLK/GPIO2_21: P1.63 P18.3
ENET1_MDC_CM: P2.60 TP8.1
ENET1_MDIO_CM: P2.62 TP9.1
ENET1_TD2_CM: P2.77 TP10.1
ENET2_MDC: P2.68 ; also on sheet 10
ENET2_MDIO: P2.70 ; also on sheet 10
ENET2_RD0: P2.41 ; also on sheet 10
ENET2_RD1: P2.43 ; also on sheet 10
ENET2_RD2: P2.45 ; also on sheet 10
ENET2_RD3: P2.47 ; also on sheet 10
ENET2_RX_CTL: P2.53 ; also on sheet 10
ENET2_RXC: P2.55 ; also on sheet 10
ENET2_TD0: P2.59 ; also on sheet 10
ENET2_TD1: P2.61 ; also on sheet 10
ENET2_TD2: P2.65 ; also on sheet 10
ENET2_TD3: P2.63 ; also on sheet 10
ENET2_TX_CTL: P2.67 ; also on sheet 10
ENET2_TXC: P2.69 ; also on sheet 10
ETH0_CT1A: C223.1 C224.1 P5.P5(CT)
ETH1_CT2A: C225.1 P5.P6(CT)
ETH1_GREEN_LED_CAT: P5.P11(LED1_C) R256.1
ETH1_LED_ACT/PHY1ADDRESS2: P2.83 P5.P12(LED1_A)
ETH1_LINK-LED_10_100: P2.86 R258.2
ETH1_LINK-LED_1000: P2.75 TP12.1
ETH1_MDI0N: P2.73 P5.P2(MDI0-)
ETH1_MDI0P: P2.74 P5.P1(MDI0+)
ETH1_MDI1N: P2.80 P5.P4(MDI1-)
ETH1_MDI1P: P2.78 P5.P3(MDI1+)
ETH1_MDI2N: P2.81 P5.P8(MDI2-)
ETH1_MDI2P: P2.79 P5.P7(MDI2+)
ETH1_MDI3N: P2.85 P5.P10(MDI3-)
ETH1_MDI3P: P2.84 P5.P9(MDI3+)
ETH1_YELLOW_LED_AN: P5.P14(LED2_A) R258.1
ETH1_YELLOW_LED_CAT: P5.P13(LED2_C) R257.1
ETH2_CT1A: C226.1 C227.1 P6.P5(CT)
ETH2_CT2A: C228.1 P6.P6(CT)
ETH2_GREEN_LED_AN: P6.P12(LED1_A) R260.2
ETH2_GREEN_LED_CAT: P6.P11(LED1_C) R259.1
ETH2_LED0/CFG_EXT: R259.2 ; also on sheet 10
ETH2_LED2/CFG_LDO1: R261.2 ; also on sheet 10
ETH2_MDI0N: P6.P2(MDI0-) ; also on sheet 10
ETH2_MDI0P: P6.P1(MDI0+) ; also on sheet 10
ETH2_MDI1N: P6.P4(MDI1-) ; also on sheet 10
ETH2_MDI1P: P6.P3(MDI1+) ; also on sheet 10
ETH2_MDI2N: P6.P8(MDI2-) ; also on sheet 10
ETH2_MDI2P: P6.P7(MDI2+) ; also on sheet 10
ETH2_MDI3N: P6.P10(MDI3-) ; also on sheet 10
ETH2_MDI3P: P6.P9(MDI3+) ; also on sheet 10
ETH2_YELLOW_LED_AN: P6.P14(LED2_A) R262.2
ETH2_YELLOW_LED_CAT: P6.P13(LED2_C) R261.1
EXP_nPWREN: Q16.5(G) R300.2 R301.1
EXP_nPWREN_G: Q16.3(D) Q17.1(G) R299.1
EXPANDER_A0: R312.2 RN1.5(RD2) U35.18(A0)
EXPANDER_A1: R314.2 RN1.6(RC2) U35.23(A1)
EXPANDER_A2: R316.2 RN1.7(RB2) U35.24(A2)
GPIO24: P18.5 R325.2
GPIO_CONTR1: P18.4 R304.1
GPIO_IO00/UART5_TXD: P1.28 P20.4
GPIO_IO01/UART5_RXD: P1.26 P20.2
GPIO_IO02/UART5_CTS: P1.30 P20.6
GPIO_IO03/UART5_RTS: P1.32 P20.3
GPIO_IO04/I2C6_SDA: P2.58 P16.3
GPIO_IO05/I2C6_SCL: P2.56 P16.5
GPIO_IO07: P1.98 ; also on sheet 10
GPIO_IO13: P1.100 R336.2 U38.2(CTRL)
GPIO_IO14/UART3_TX: P2.76 P19.4
GPIO_IO15/UART3_RX: P1.60 P19.2
GPIO_IO16: P1.96 ; also on sheet 10
GPIO_IO17: P1.95 P18.7
GPIO_IO18/TPM_CH2: P1.89 P18.2
GPIO_IO22/TPM5_CH1: P1.79 P18.9
GPIO_IO23/SPDIF_TX: C249.2 P1.81
GPIO_IO24: R114.1 R325.1
GPIO_IO25/CAN2_TX: P1.33 U33.1(TXD)
GPIO_IO27/CAN2_RX: P1.49 U33.4(RXD)
HASW_EN: E11.1 R283.1 U31.10(SEL) U32.5(EN)
HASW_IP1: R278.1 U29.8(IP)
HASW_IP2: R284.1 U32.8(IP)
HOSTA_USB_DN: J3.2(D-) L19.4
HOSTA_USB_DP: J3.3(D+) L19.3
HOSTB_USB_DN: J2.2(D-) L21.4
HOSTB_USB_DP: J2.3(D+) L21.3
HP_FB: R111.1 U16.B4(HPOUTFB)
HP_J_D: J6.CN R216.1 R217.1
HP_JD: R124.2 R216.2 U16.G1(GPIO5)
HP_L: C112.2 R110.1
HP_MICH: TP4.1 U16.F4(CLKOUT3/GPIO3)
HP_R: C100.2 R104.1
HPOUT_L: C112.1 L18.2 R214.1 U16.B5(HPOUTL)
HPOUT_R: C100.1 L17.2 R215.1 U16.A5(HPOUTR)
HUB_OE: R282.2 U31.8(\\~{O}E)
I2C3_SCK: P1.94 ; also on sheet 11
I2C3_SCL_CM: J4.16 P13.1 R123.2 U35.19(SCL) U37.1(IO1) ; also on sheet 11
I2C3_SDA: P1.91 ; also on sheet 11
I2C3_SDA_CM: J4.18 P13.3 R122.2 U35.20(SDA) U37.3(IO2) ; also on sheet 11
ID_VBUS_SEL: R267.2 R269.1 U28.6(SEL) U30.6(SEL)
INT_DISP: P13.5 R333.1 U37.4(IO3)
INT_EXP: R307.2 R309.1 U35.22(\\~{IN}T)
J6_CO: J6.CO R218.2
J_HPOUT_L: C199.2 J6.4(L) L18.1
J_HPOUT_R: C194.2 J6.3(R) L17.1
JTAG_TCK: P1.73 ; also on sheet 11
JTAG_TDI: P1.71 ; also on sheet 11
JTAG_TDO: P1.67 ; also on sheet 11
JTAG_TMS: P1.65 ; also on sheet 11
LLINE_IN: C93.2 J5.4(L)
LLINEIN: C92.2 C93.1 U16.E6(IN4L)
LVDS_CLK_N: L32.4 P2.14
LVDS_CLK_P: L32.3 P2.12
LVDS_CLKN: L32.1 P14.5
LVDS_CLKP: L32.2 P14.3
LVDS_COMP: C273.1 U38.5(COMP)
LVDS_DISP_RESET: P14.17 R313.1
LVDS_LED_NEG: C268.1 P14.15 R338.1 R339.1 U38.6(FB)
LVDS_LED_POS: C268.2 C272.1 D5.CATHODE P14.19
LVDS_N0: L28.1 P14.6
LVDS_N1: L29.1 P14.11
LVDS_N2: L30.1 P14.12
LVDS_N3: L31.1 P14.18
LVDS_P0: L28.2 P14.4
LVDS_P1: L29.2 P14.9
LVDS_P2: L30.2 P14.10
LVDS_P3: L31.2 P14.16
LVDS_RESET: R338.2 R339.2 R340.1
LVDS_SW_PWR_IN: C270.1 C271.1 L33.1 R334.2 R336.1 U38.1(IN)
LVDS_TX0_N: L28.4 P2.26
LVDS_TX0_P: L28.3 P2.24
LVDS_TX1_N: L29.4 P2.20
LVDS_TX1_P: L29.3 P2.18
LVDS_TX2_N: L30.4 P2.8
LVDS_TX2_P: L30.3 P2.6
LVDS_TX3_N: L31.4 P2.4
LVDS_TX3_P: L31.3 P2.2
LVDS_WLD_SW: D5.ANODE L33.2 U38.3(SW)
MICBIAS: C111.1 U16.A4(MICBIAS)
MODEM_RST: R322.1 ; also on sheet 11
mux_PCIe_USB_DN: U31.7(HSD1-) ; also on sheet 11
mux_PCIe_USB_DP: U31.1(HSD1+) ; also on sheet 11
MUX_USB1_DN: L19.1 U27.7(HSD1-)
MUX_USB1_DP: L19.2 U27.1(HSD1+)
MUX_USB2_DN: L21.1 U31.6(HSD2-)
MUX_USB2_DP: L21.2 U31.2(HSD2+)
MUX_USB3_SEL: Q16.2(G) R275.2 R279.2
PB_ALT_BOOT: E3.1 R239.2 SW2.2 SW2.4
PB_RESET: R238.2 SW3.2 SW3.4
PB_SDWN_ENH: E4.2 R240.1
PDM_CLK/GPIO1_8: P1.21 P18.6 R300.1
PDM_DATA0: P1.23 R309.2
PMIC_ON_REQ: P1.68 P10.6 ; also on sheet 13
PMIC_STBY_REQ: P1.66 P10.4 ; also on sheet 13
POR_B_3P3: P2.66 P10.5 ; also on sheet 11
PWRBTN: P2.64 R237.1
Q11_D: Q11.3(DRAIN) R243.2 R244.2
Q12_D: Q12.3(DRAIN) R245.2 R246.2
Q13_D: Q13.3(DRAIN) R247.2 R248.2
Q14_D: Q14.3(DRAIN) R249.2 R250.2
Q15_D: Q15.3(DRAIN) R251.2 R252.2
RF_KILL#: R323.1 ; also on sheet 11
RLINE_IN: C190.2 J5.3(R)
RLINEIN: C189.2 C190.1 U16.E7(IN4R)
SAI1_RXD0: P1.45 U16.D2(ADCDAT)
SAI1_TXC/CAN1_RX: P1.51 U16.E1(BCLK)
SD2_CLK: P2.96 ; also on sheet 11
SD2_CMD: P2.100 ; also on sheet 11
SD2_DATA0: P2.97 ; also on sheet 11
SD2_DATA1: P2.99 ; also on sheet 11
SD2_DATA2: P2.94 ; also on sheet 11
SD2_DATA3: P2.98 ; also on sheet 11
SD2_nCD: P2.92 ; also on sheet 11
SD2_nRST: P2.51 TP1.1
SD3_CLK: P2.36 P22.2
SD3_CMD: P2.38 P22.4
SD3_DATA0: P2.42 P22.6
SD3_DATA1: P2.44 P22.7
SD3_DATA2: P2.48 P22.3
SD3_DATA3: P2.50 P22.5
SDWN_ENH: E4.1 P2.88
SPDIF_AUDIO_OUT: C250.1 P10.2 R294.2 R295.1
SPDIF_OUT1C: C249.1 R294.1
SW_SAI1_TXD0/CAN1_TX: P1.53 U16.D1(DACDAT)
SW_SAI1_TXFS: P1.87 U16.D3(LRCLK)
SW_UART1_TXD: P1.74 ; also on sheet 11
SW_UART2_TXD: P1.72 P18.8
SWPWRBTN: R237.2 SW4.2 SW4.4
SYS_RST_PMIC: P1.2 P10.3 R238.1 ; also on sheet 11
TESTPOINT3: P1.84 TP6.1
TESTPOINT4: P1.92 TP7.1
TESTPOINT5: P2.90 TP11.1
TOUCH_RESET: P13.7 R311.1 U37.6(IO4)
U28_IN0: R277.2 U30.3(B0)
U28_OUT: R276.1 U30.4(A)
U29_EN: Q16.6(D) R274.1 U29.5(EN)
U31_IN0: R265.2 U28.3(B0)
U31_IN1: R264.2 U28.1(B1)
U31_OUT: R266.1 U28.4(A)
U32_OEL: R270.2 U27.8(\\~{O}E)
UART1_RXD: P1.76 ; also on sheet 11
UART2_RXD/GPIO1_IO6/SAI1_MCLK: P1.19 R112.2
USB1_DN: P1.14 U27.5(D-)
USB1_DP: P1.12 U27.3(D+)
USB1_ID: P1.22 R276.2
USB1_SEL: R268.1 U27.10(SEL)
USB1_VBUS_3V3: P1.24 R263.2 R266.2
USB1SEL: R268.2 R271.1 R272.1
USB2_DN: P1.5 U31.5(D-)
USB2_DP: P1.3 U31.3(D+)
USB2_ID: P1.7 R280.1
USB2_VBUS_3V3: P1.1 R281.2
USB_SDM_DN: L20.1 U27.6(HSD2-)
USB_SDM_DP: L20.2 U27.2(HSD2+)
USBSD_VBUS: C233.1 C234.2 P21.1(VBUS) R240.2 R264.1 R267.1 R271.2 R275.1
USBSDM_DN: L20.4 P21.2(D-)
USBSDM_DP: L20.3 P21.3(D+)
User_LED1: Q18.2(G1) R303.2 R306.1
User_LED2: Q18.5(G2) R302.2 R308.1
uUSB_ID: P21.4(ID) R273.1 U30.1(B1)
V_SOM: C200.2 C201.2 C202.1 C203.2 C204.2 C205.2 C206.2 C207.1 C208.1 C209.1 C210.1 C211.1 C212.1 C213.1 C214.1 C215.1 C216.1 C217.1 C218.1 P1.11 P1.27 P1.43 P1.57 P1.69 P1.83 P2.9 P2.19 P2.29 P2.39 P2.57 P2.71 P2.87 R243.1 R244.1 ; also on sheet 12 13
VDC_IN: C220.1 C221.1 Q1.5(D) Q1.6(D) Q1.7(D) Q1.8(D) Q1.9(D-pad) R251.1 R252.1 ; also on sheet 13
VGS_Q1: C219.2 Q1.4(G) R242.1 R253.1
VMIDC: C103.2 U16.C5(VMIDC)
VSD_3V3: P1.17 ; also on sheet 11
XTALI_24M: C95.2 R105.1 R112.1 U16.G7(MCLK/XTI) X4.1
XTALO_24M: C94.2 R105.2 U16.F7(XTO) X4.3

Not connected (* = marked no-connect by the designer): J4 9 11 15* 17 27* 28* 29* 30* 33* 34* 35* 36* 39* 40* 41* 42* 44* 45* 46* 47* 48*; J5 2(AUX) CN* CO*; J6 2(AUX); P1 6* 8* 9* 13* 15* 16* 18* 25 29* 31* 34* 36* 38* 42* 44* 46* 47* 48* 50* 52* 55* 56* 62* 70* 77* 85* 86* 97* 99*; P2 25 27 49* 52*; P9 5* 7*; P10 7; P13 4* 6*; P15 6* 7*; P16 2* 4* 6* 7*; P17 3* 4* 5* 7*; P19 3* 5* 6* 7*; P20 5* 7*; R315 1*; R321 1*; R324 1*; RN1 1(RA1)* 8(RA2)*; U16 A1(SPKOUTLP) B2(SPKOUTRP) B3(SPKOUTLN) C3(SPKOUTRN) C4(IN1L)* D4(IN1R)* D5(IN2L)* E5(IN2R)* F5(IN3L)* F6(IN3R)*; U29 1(FLG)*; U32 1(FLG)*

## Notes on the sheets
sheet 1
- SBEV-UCMIMX93
- BOARD REVISION: 1.0
- Page
- Description
- 01
- Index and Block Diagram
- 02
- SOM Connectors
- 03
- DC INP, Discharge
- 04
- Ethernet Connectors
- 05
- Gbe PHY2
- Codec
- 06
- 07
- MIPI-DSI LCD
- 08
- LVDS LCD
- 09
- SPDIF,CAN, CSI,MISC
- 10
- Console, RS232, SD, miniPCIe
- 11
- USB
- 12
- Power
- 13
- Mechanical
sheet 2
- SOM connectors
- Power button
- UART5_RXD_BT
- UART5_TXD_BT
- UART5_CTS_BT
- UART5_RTS_BT
- RESET
- SD boot
- A53 core console
  UART1
- RESERVED#1
- RESERVED#2
- SDP (USB) boot
- 10K PD  on the Module
- Tamper
- RESERVED#3
sheet 3
- DC input
- Vin 8V-18V
  Imax (vin=10V) =3.31A
- Discharge
- P-MOSFET, 8.3A, 20V
- -Vgs:2-4.5V
- 3A, 20V
- Vgs:2.7-6.0V
sheet 4
- 100 Ohm
- 100 Ohm
- 100 Ohm
- 100 Ohm
- Ethernet 1 connector
- 100 Ohm
- 100 Ohm
- 100 Ohm
- Ethernet 2 connector
- 100 Ohm
sheet 5
- USB1
- Host with mux for SDP mode
- DNP
- Mux for USB1 ID and VBUS
- NOTE: USB1 multiplexing is controlled by presence of VBUS on connector P21
- 90 ohm
- # 90-Ohm differential pairs
- # 90-Ohm diff pairs
- Assembly ACAP to L23
- 1.05A LIMIT
- Serial Download mode
  (microUSB2.0 Type B)
- DNP
- USB2
- Host with mux for miniPCIe socket P18
- NOTE: USB1 multiplexing is controlled by jumper E11
- # 90-Ohm diff pairs
- 1.05A LIMIT
- E11 operation
  Open:       for USB conn. J6
  Close:      for miniPCIe socket P18
sheet 6
- CAN bus
- User LEDs
- GPIO expander reset
- DNP
- DNP
- DNP
- System /Miscellaneous
- GPIO expander
- Camera Edge Connector
- ALT 5: gpio1.IO[9]
- DNP
- DNP
- DNP
- CSI_D2_P
- DNP
- CSI_D2_N
- CSI1
- CSI_D3_P
- CSI_D3_N
- CSIB_CLK_P
- CSIB_D0_P
- CSIB_CLK_N
- CSIB_D0_N
- CSIB_D1_P
- CSIB_D2_P
- CSI2
- I2C Address:
  0x20
- CSIB_D1_N
- CSIB_D2_N
- I2C_SCL
- I2C_SDA
- CSIB_D3_N
- CSIB_D3_P
- CONTROL_B
- CONTROL_B
- CONTROL_B
- CONTROL_B
- CONTROL_B
- Boot mode
- #BOOT_MODE0
- #BOOT_MODE1
- #BOOT_MODE2
- UART
- #BOOT_MODE3
- UART5_RXD
- UART5_CTS
- UART5_TXD
- UART5_RTS
- ADC/TPM (PWM)
- I2C
- GPIO
- ECSPI
- UART7_RX
- UART7_TX
- Output only
sheet 7
- PLUGGED: High
  Removed: Low
- CODEC
- DNP
- DNP
- DNP
- DNP
- i
- o
- SAI1_MCLK
- DNP
- DNP
- DNP
- DNP
sheet 8
- MIPI-DSI LCD Int.
- # 100-Ohm diff pairs
- # 100-Ohm diff pairs
- MIPI LCD back-light power
- Typical LED configuration: Two parallel
  chains of 6 serially connected LEDs
- 19.2V/40mA
- DNP
sheet 9
- LVDS LCD Int.
- # 100-Ohm diff pairs
- # 100-Ohm diff pairs
- LVDS/DSI touch panel connector
- LVDS LCD back-light power
- 9.6V/270mA
- SPDIF_RX = PWM2_OUT
- DNP
